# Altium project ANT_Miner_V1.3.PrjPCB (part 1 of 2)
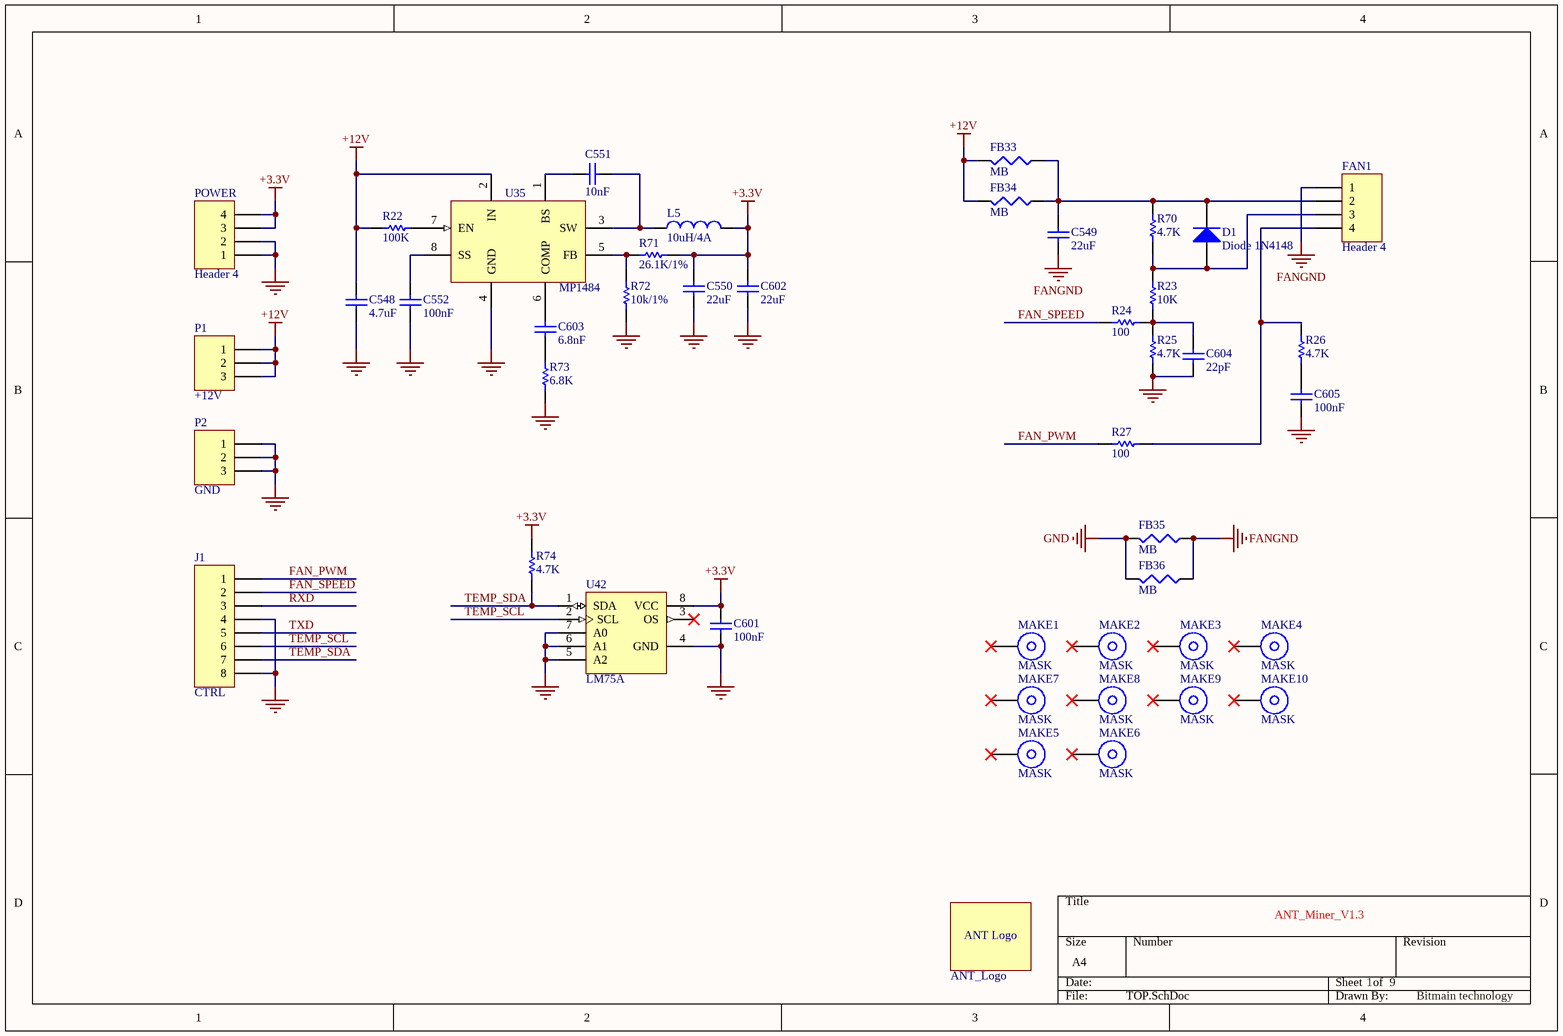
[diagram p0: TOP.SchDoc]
9 sheets, 987 parts. Net scope: global (net labels, ports and power ports of the same name join across sheets).
Board file: BitMainTech_V1.3.PcbDoc
Sheets:
  TOP.SchDoc
  HashPower1.SchDoc
  HashPower2.SchDoc
  HashPower3.SchDoc
  HashPower4.SchDoc
  HashUnit1.SchDoc
  HashUnit2.SchDoc
  HashUnit3.SchDoc
  HashUnit4.SchDoc

## Sheet TOP.SchDoc: ANT_Miner_V1.3
size A4; Date: 2013/11/20; DrawnBy: Bitmain technology; SheetNumber: 1; SheetTotal: 9

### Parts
C548  4.7uF  [CAP1210(3225)_TAN]
C549  22uF  [CAP1210(3225)_TAN]
C550  22uF  [CAP1210(3225)_TAN]
C551  10nF  [CC0603(1608)]
C552  100nF  [CC0603(1608)]
C601  100nF  [CC0603(1608)]
C602  22uF  [CAP1210(3225)_TAN]
C603  6.8nF  [CC0603(1608)]
C604  22pF  [CC0603(1608)]
C605  100nF  [CC0603(1608)]
D1  Diode 1N4148  [CD3216-1206]
FAN1  Header 4  [4PINFAN]
FB33  MB  [INDC3216L]
FB34  MB  [INDC3216L]
FB35  MB  [INDC3216L]
FB36  MB  [INDC3216L]
J1  CTRL  [8Pin_180]
L5  10uH/4A  [SMD_L_7.4x7.4]
MAKE1  MASK  [MASK]
MAKE2  MASK  [MASK]
MAKE3  MASK  [MASK]
MAKE4  MASK  [MASK]
MAKE5  MASK  [MASK]
MAKE6  MASK  [MASK]
MAKE7  MASK  [MASK]
MAKE8  MASK  [MASK]
MAKE9  MASK  [MASK]
MAKE10  MASK  [MASK]
P1  +12V  [TERMINAL_3]
P2  GND  [TERMINAL_3]
POWER  Header 4  [4Pin_180]
R22  100K  [RR0603(1608)]
R23  10K  [RR0603(1608)]
R24  100  [RR0603(1608)]
R25  4.7K  [RR0603(1608)]
R26  4.7K  [RR0603(1608)]
R27  100  [RR0603(1608)]
R70  4.7K  [RR0603(1608)]
R71  26.1K/1%  [RR0603(1608)]
R72  10k/1%  [RR0603(1608)]
R73  6.8K  [RR0603(1608)]
R74  4.7K  [RR0603(1608)]
U35  MP1484  [SOIC8L]
U42  LM75A  [SO8_L]
  ANT_Logo  [ANT_Logo_930x370]

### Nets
+3.3V: C550.2 C601.1 C602.2 L5.2 POWER.3 POWER.4 R71.1 R74.2 U42.8(VCC)
+12V: C548.2 FB33.2 FB34.2 P1.1 P1.2 P1.3 R22.2 U35.2(IN)
FANGND: C549.1 FAN1.1 FB35.1 FB36.1
GND: C548.1 C550.1 C552.2 C601.2 C602.1 C604.2 C605.2 FB35.2 FB36.2 J1.4 J1.8 P2.1 P2.2 P2.3 POWER.1 POWER.2 R25.1 R72.1 R73.1 U35.0 U35.4(GND) U42.4(GND) U42.5(A2) U42.6(A1) U42.7(A0)
FAN_PWM: J1.1 R27.2
FAN_SPEED: J1.2 R24.2
RXD: J1.3
TEMP_SCL: J1.6 U42.2(SCL)
TEMP_SDA: J1.7 R74.1 U42.1(SDA)
TXD: J1.5
NetC549_2: C549.2 D1.2(K) FAN1.2 FB33.1 FB34.1 R70.2
NetC551_1: C551.1 U35.1(BS)
NetC551_2: C551.2 L5.1 U35.3(SW)
NetC552_1: C552.1 U35.8(SS)
NetC603_1: C603.1 U35.6(COMP)
NetC603_2: C603.2 R73.2
NetC604_1: C604.1 R23.2 R24.1 R25.2
NetC605_1: C605.1 R26.1
NetD1_1: D1.1(A) FAN1.3 R23.1 R70.1
NetFAN1_4: FAN1.4 R26.2 R27.1
NetR22_1: R22.1 U35.7(EN)
NetR71_2: R71.2 R72.2 U35.5(FB)

Not connected (* = marked no-connect by the designer): MAKE1 1*; MAKE2 1*; MAKE3 1*; MAKE4 1*; MAKE5 1*; MAKE6 1*; MAKE7 1*; MAKE8 1*; MAKE9 1*; MAKE10 1*; U42 3(OS)*

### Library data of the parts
C548-C552 C601-C605 = Cap Semi: Capacitor (Semiconductor SIM Model)
D1 = Diode 1N4148: High Conductance Fast Diode
FAN1 POWER = Header 4: Header, 4-Pin
FB33-FB36 = Res3: Resistor
J1 = Header 8: Header, 8-Pin
L5 = Inductor: Code_IEC: 1005
P1 P2 = Header 3: Header, 3-Pin
R22-R27 R70-R74 = Res1: Resistor
U42 = LM75A: NXP Digital temperature sensor and thermal watchdog

## Sheet HashPower1.SchDoc: ANT_Miner_V1.3
size A4; Date: 2013/11/20; DrawnBy: Bitmain Technology; SheetNumber: 2; SheetTotal: 9
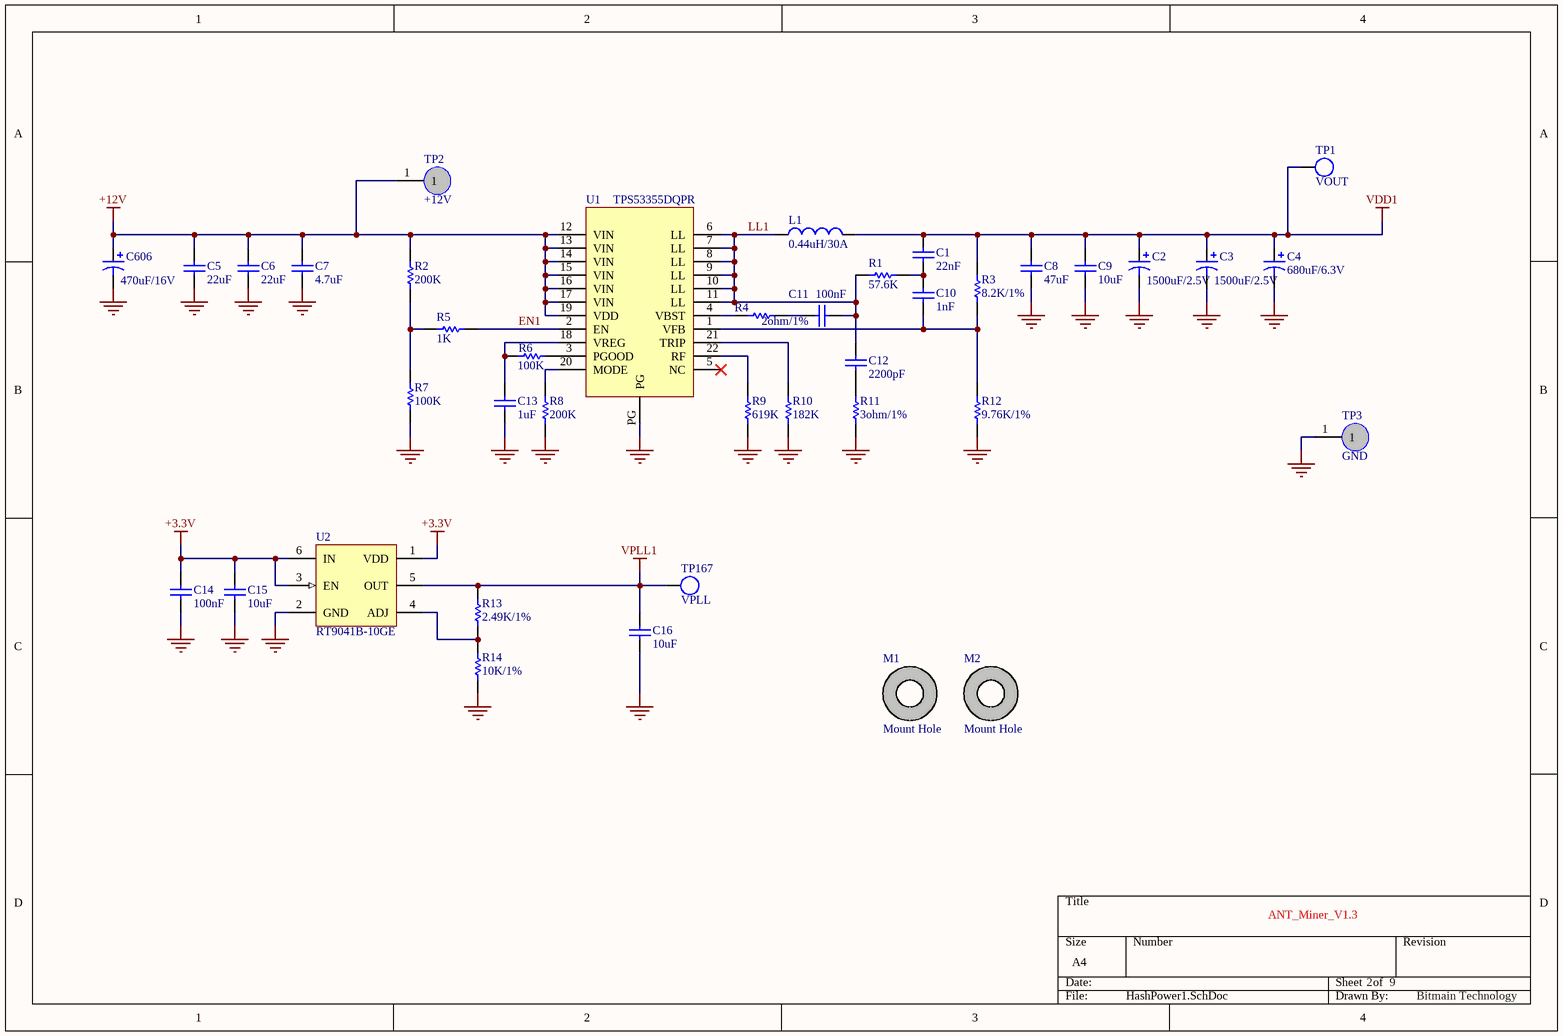
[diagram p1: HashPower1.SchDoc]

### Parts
C1  22nF  [CC0603(1608)]
C2  value 1500uF/2.5V  [F12]  (hidden comment: 1500uF/4V)
C3  value 1500uF/2.5V  [F12]  (hidden comment: 1500uF/4V)
C4  680uF/6.3V  [D]
C5  22uF  [CC1210(3225)]
C6  22uF  [CC1210(3225)]
C7  4.7uF  [CC0805(2012)]
C8  47uF  [CAPC3225L]
C9  10uF  [CAPC2012L]
C10  1nF  [CC0603(1608)]
C11  100nF  [CC0603(1608)]
C12  2200pF  [CC0603(1608)]
C13  1uF  [CC0603(1608)]
C14  100nF  [CC0603(1608)]
C15  10uF  [CC0805(2012)]
C16  10uF  [CC0805(2012)]
C606  470uF/16V  [E12]
L1  0.44uH/30A  [IHLP5050]
M1  Mount Hole  [HOLE_3.2]
M2  Mount Hole  [HOLE_3.2]
R1  57.6K  [RR0603(1608)]
R2  200K  [RR0603(1608)]
R3  8.2K/1%  [RR0603(1608)]
R4  value 2ohm/1%  [RR0603(1608)]  (hidden comment: 2)
R5  1K  [RR0603(1608)]
R6  100K  [RR0603(1608)]
R7  100K  [RR0603(1608)]
R8  200K  [RR0603(1608)]
R9  619K  [RR0603(1608)]
R10  182K  [RR0603(1608)]
R11  value 3ohm/1%  [RR0603(1608)]  (hidden comment: 3)
R12  9.76K/1%  [RR0603(1608)]
R13  2.49K/1%  [RR0603(1608)]
R14  10K/1%  [RR0603(1608)]
TP1  VOUT  [TP_SMD_1.0]
TP2  +12V  [TP]
TP3  GND  [TP]
TP167  VPLL  [TP_SMD_1.0]
U1  TPS53355DQPR  [TPS53355]
U2  RT9041B-10GE  [SOT23-6_L]

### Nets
+3.3V: C14.2 C15.2 U2.1(VDD) U2.3(EN) U2.6(IN)
+12V: C5.1 C6.1 C7.1 C606.1 R2.1 TP2.1 U1.12(VIN) U1.13(VIN) U1.14(VIN) U1.15(VIN) U1.16(VIN) U1.17(VIN) U1.19(VDD)
GND: C2.2 C3.2 C4.2 C5.2 C6.2 C7.2 C8.1 C9.1 C13.2 C14.1 C15.1 C16.1 C606.2 R7.2 R8.2 R9.2 R10.2 R11.2 R12.2 R14.1 TP3.1 U1.PG U2.2(GND)
VDD1: C1.1 C2.1 C3.1 C4.1 C8.2 C9.2 L1.2 R3.1 TP1.1
VPLL1: C16.2 R13.2 TP167.1 U2.5(OUT)
EN1: R5.2 U1.2(EN)
LL1: C11.2 C12.1 L1.1 R1.1 U1.6(LL) U1.7(LL) U1.8(LL) U1.9(LL) U1.10(LL) U1.11(LL)
NetC1_2: C1.2 C10.1 R1.2
NetC10_2: C10.2 R3.2 R12.1 U1.1(VFB)
NetC11_1: C11.1 R4.2
NetC12_2: C12.2 R11.1
NetC13_1: C13.1 R6.1 U1.18(VREG)
NetR2_2: R2.2 R5.1 R7.1
NetR4_1: R4.1 U1.4(VBST)
NetR6_2: R6.2 U1.3(PGOOD)
NetR8_1: R8.1 U1.20(MODE)
NetR9_1: R9.1 U1.22(RF)
NetR10_1: R10.1 U1.21(TRIP)
NetR13_1: R13.1 R14.2 U2.4(ADJ)

Not connected (* = marked no-connect by the designer): M1 0(PIN); M2 0(PIN); U1 5(NC)*

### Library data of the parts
C1 C5-C7 C10-C13 = Cap: Capacitor
C2 C3 C606 = Cap Pol2: Polarized Capacitor (SMD)
C4 = Cap Pol3: Polarized Capacitor (Surface Mount)
C8 C9 C14-C16 = Cap Semi: Capacitor (Semiconductor SIM Model)
L1 = Inductor: Code_IEC: 1005
M1 M2 = M_Hole
R1-R14 = Res1: Resistor
TP1 TP167 = TP: Test Point
TP2 TP3 = TP
U1 = TPS53355: TI DC-DC,Output 30A.

## Sheet HashPower2.SchDoc: ANT_Miner_V1.3
size A4; Date: 2013/11/20; DrawnBy: Bitmain Technology; SheetNumber: 3; SheetTotal: 9
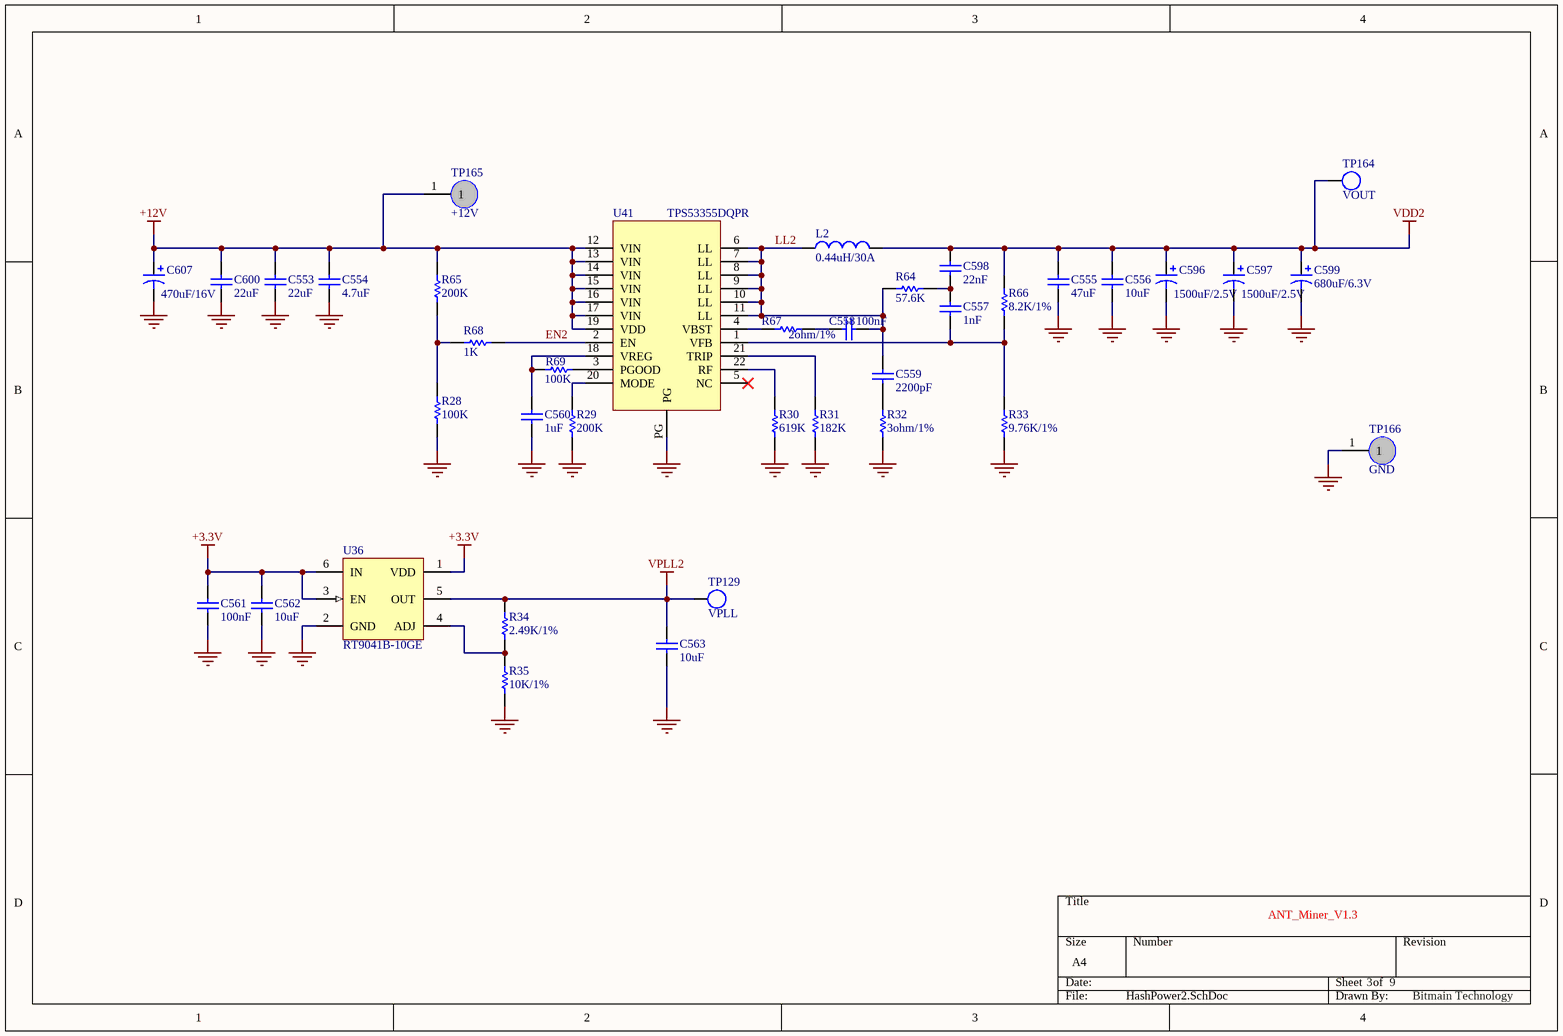
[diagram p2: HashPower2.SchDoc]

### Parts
C553  22uF  [CC1210(3225)]
C554  4.7uF  [CC0805(2012)]
C555  47uF  [CAPC3225L]
C556  10uF  [CAPC2012L]
C557  1nF  [CC0603(1608)]
C558  100nF  [CC0603(1608)]
C559  2200pF  [CC0603(1608)]
C560  1uF  [CC0603(1608)]
C561  100nF  [CC0603(1608)]
C562  10uF  [CC0805(2012)]
C563  10uF  [CC0805(2012)]
C596  value 1500uF/2.5V  [F12]  (hidden comment: 1500uF/4V)
C597  value 1500uF/2.5V  [F12]  (hidden comment: 1500uF/4V)
C598  22nF  [CC0603(1608)]
C599  680uF/6.3V  [D]
C600  22uF  [CC1210(3225)]
C607  470uF/16V  [E12]
L2  0.44uH/30A  [IHLP5050]
R28  100K  [RR0603(1608)]
R29  200K  [RR0603(1608)]
R30  619K  [RR0603(1608)]
R31  182K  [RR0603(1608)]
R32  value 3ohm/1%  [RR0603(1608)]  (hidden comment: 3)
R33  9.76K/1%  [RR0603(1608)]
R34  2.49K/1%  [RR0603(1608)]
R35  10K/1%  [RR0603(1608)]
R64  57.6K  [RR0603(1608)]
R65  200K  [RR0603(1608)]
R66  8.2K/1%  [RR0603(1608)]
R67  value 2ohm/1%  [RR0603(1608)]  (hidden comment: 2)
R68  1K  [RR0603(1608)]
R69  100K  [RR0603(1608)]
TP129  VPLL  [TP_SMD_1.0]
TP164  VOUT  [TP_SMD_1.0]
TP165  +12V  [TP]
TP166  GND  [TP]
U36  RT9041B-10GE  [SOT23-6_L]
U41  TPS53355DQPR  [TPS53355]

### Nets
+3.3V: C561.2 C562.2 U36.1(VDD) U36.3(EN) U36.6(IN)
+12V: C553.1 C554.1 C600.1 C607.1 R65.1 TP165.1 U41.12(VIN) U41.13(VIN) U41.14(VIN) U41.15(VIN) U41.16(VIN) U41.17(VIN) U41.19(VDD)
GND: C553.2 C554.2 C555.1 C556.1 C560.2 C561.1 C562.1 C563.1 C596.2 C597.2 C599.2 C600.2 C607.2 R28.2 R29.2 R30.2 R31.2 R32.2 R33.2 R35.1 TP166.1 U36.2(GND) U41.PG
VDD2: C555.2 C556.2 C596.1 C597.1 C598.1 C599.1 L2.2 R66.1 TP164.1
VPLL2: C563.2 R34.2 TP129.1 U36.5(OUT)
EN2: R68.2 U41.2(EN)
LL2: C558.2 C559.1 L2.1 R64.1 U41.6(LL) U41.7(LL) U41.8(LL) U41.9(LL) U41.10(LL) U41.11(LL)
NetC557_1: C557.1 C598.2 R64.2
NetC557_2: C557.2 R33.1 R66.2 U41.1(VFB)
NetC558_1: C558.1 R67.2
NetC559_2: C559.2 R32.1
NetC560_1: C560.1 R69.1 U41.18(VREG)
NetR28_1: R28.1 R65.2 R68.1
NetR29_1: R29.1 U41.20(MODE)
NetR30_1: R30.1 U41.22(RF)
NetR31_1: R31.1 U41.21(TRIP)
NetR34_1: R34.1 R35.2 U36.4(ADJ)
NetR67_1: R67.1 U41.4(VBST)
NetR69_2: R69.2 U41.3(PGOOD)

Not connected (* = marked no-connect by the designer): U41 5(NC)*

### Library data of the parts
C553 C554 C557-C560 C598 C600 = Cap: Capacitor
C555 C556 C561-C563 = Cap Semi: Capacitor (Semiconductor SIM Model)
C596 C597 C607 = Cap Pol2: Polarized Capacitor (SMD)
C599 = Cap Pol3: Polarized Capacitor (Surface Mount)
L2 = Inductor: Code_IEC: 1005
R28-R35 R64-R69 = Res1: Resistor
TP129 TP164 = TP: Test Point
TP165 TP166 = TP
U41 = TPS53355

## Sheet HashPower3.SchDoc: ANT_Miner_V1.3
size A4; Date: 2013/11/20; DrawnBy: Bitmain Technology; SheetNumber: 4; SheetTotal: 9
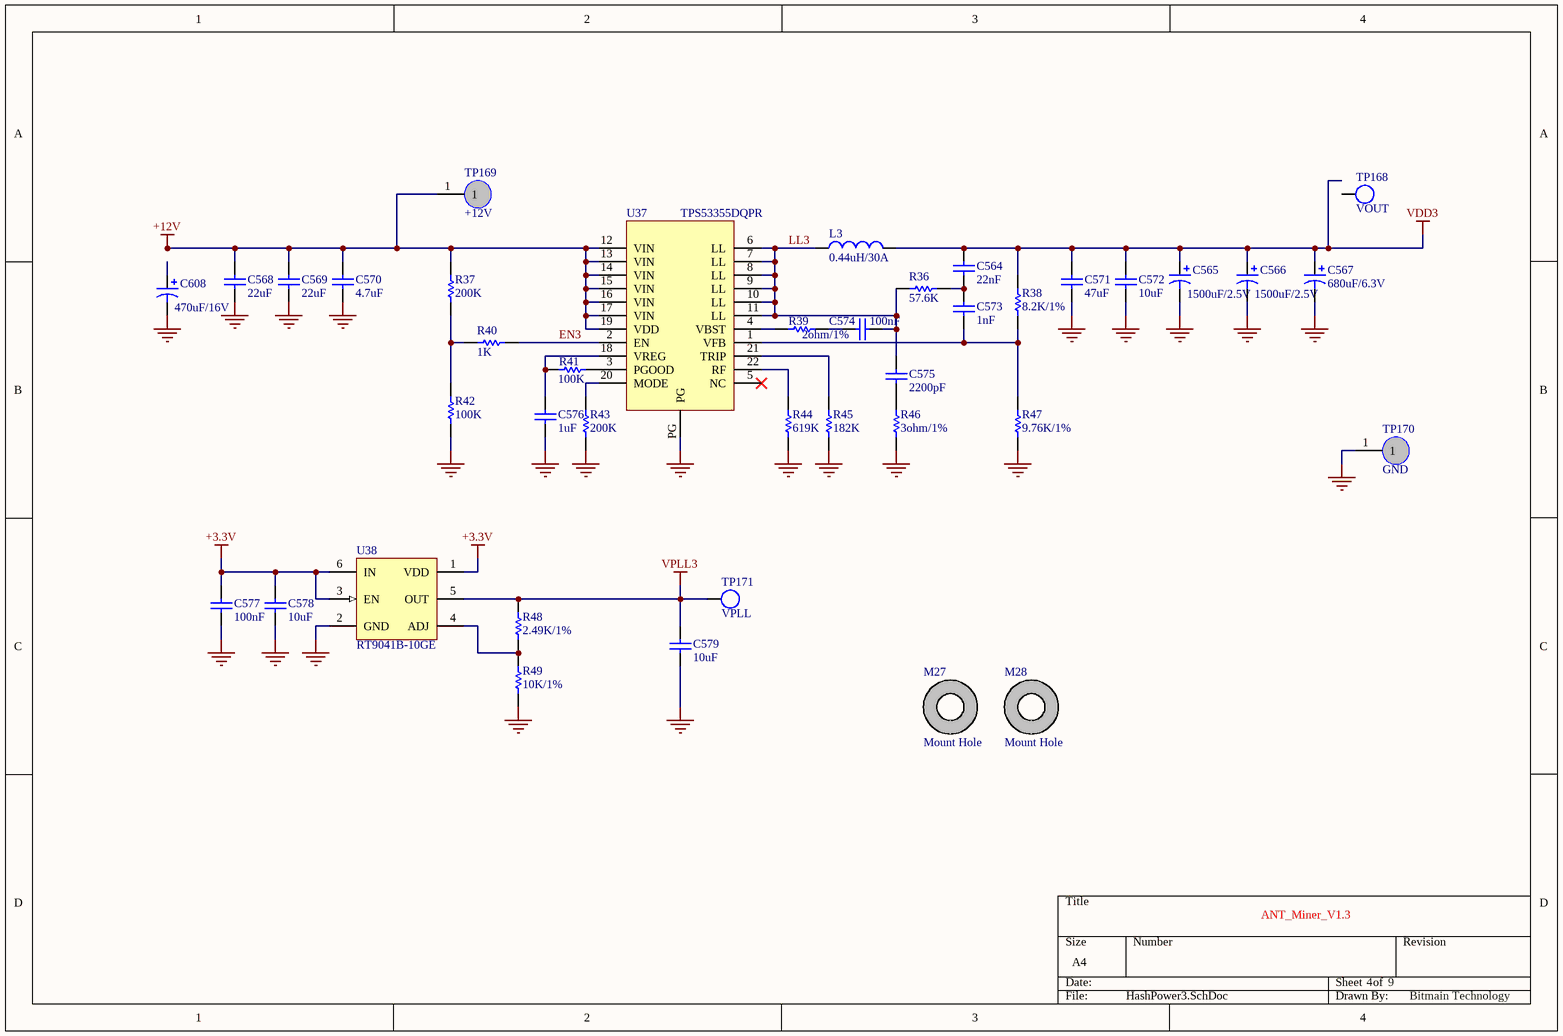
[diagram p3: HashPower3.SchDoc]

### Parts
C564  22nF  [CC0603(1608)]
C565  value 1500uF/2.5V  [F12]  (hidden comment: 1500uF/4V)
C566  value 1500uF/2.5V  [F12]  (hidden comment: 1500uF/4V)
C567  680uF/6.3V  [D]
C568  22uF  [CC1210(3225)]
C569  22uF  [CC1210(3225)]
C570  4.7uF  [CC0805(2012)]
C571  47uF  [CAPC3225L]
C572  10uF  [CAPC2012L]
C573  1nF  [CC0603(1608)]
C574  100nF  [CC0603(1608)]
C575  2200pF  [CC0603(1608)]
C576  1uF  [CC0603(1608)]
C577  100nF  [CC0603(1608)]
C578  10uF  [CC0805(2012)]
C579  10uF  [CC0805(2012)]
C608  470uF/16V  [E12]
L3  0.44uH/30A  [IHLP5050]
M27  Mount Hole  [HOLE_3.2]
M28  Mount Hole  [HOLE_3.2]
R36  57.6K  [RR0603(1608)]
R37  200K  [RR0603(1608)]
R38  8.2K/1%  [RR0603(1608)]
R39  value 2ohm/1%  [RR0603(1608)]  (hidden comment: 2)
R40  1K  [RR0603(1608)]
R41  100K  [RR0603(1608)]
R42  100K  [RR0603(1608)]
R43  200K  [RR0603(1608)]
R44  619K  [RR0603(1608)]
R45  182K  [RR0603(1608)]
R46  value 3ohm/1%  [RR0603(1608)]  (hidden comment: 3)
R47  9.76K/1%  [RR0603(1608)]
R48  2.49K/1%  [RR0603(1608)]
R49  10K/1%  [RR0603(1608)]
TP168  VOUT  [TP_SMD_1.0]
TP169  +12V  [TP]
TP170  GND  [TP]
TP171  VPLL  [TP_SMD_1.0]
U37  TPS53355DQPR  [TPS53355]
U38  RT9041B-10GE  [SOT23-6_L]

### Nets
+3.3V: C577.2 C578.2 U38.1(VDD) U38.3(EN) U38.6(IN)
+12V: C568.1 C569.1 C570.1 R37.1 TP169.1 U37.12(VIN) U37.13(VIN) U37.14(VIN) U37.15(VIN) U37.16(VIN) U37.17(VIN) U37.19(VDD)
GND: C565.2 C566.2 C567.2 C568.2 C569.2 C570.2 C571.1 C572.1 C576.2 C577.1 C578.1 C579.1 C608.2 R42.2 R43.2 R44.2 R45.2 R46.2 R47.2 R49.1 TP170.1 U37.PG U38.2(GND)
VDD3: C564.1 C565.1 C566.1 C567.1 C571.2 C572.2 L3.2 R38.1
VPLL3: C579.2 R48.2 TP171.1 U38.5(OUT)
EN3: R40.2 U37.2(EN)
LL3: C574.2 C575.1 L3.1 R36.1 U37.6(LL) U37.7(LL) U37.8(LL) U37.9(LL) U37.10(LL) U37.11(LL)
NetC564_2: C564.2 C573.1 R36.2
NetC573_2: C573.2 R38.2 R47.1 U37.1(VFB)
NetC574_1: C574.1 R39.2
NetC575_2: C575.2 R46.1
NetC576_1: C576.1 R41.1 U37.18(VREG)
NetR37_2: R37.2 R40.1 R42.1
NetR39_1: R39.1 U37.4(VBST)
NetR41_2: R41.2 U37.3(PGOOD)
NetR43_1: R43.1 U37.20(MODE)
NetR44_1: R44.1 U37.22(RF)
NetR45_1: R45.1 U37.21(TRIP)
NetR48_1: R48.1 R49.2 U38.4(ADJ)

Not connected (* = marked no-connect by the designer): C608 1; M27 0(PIN); M28 0(PIN); TP168 1; U37 5(NC)*

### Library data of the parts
C564 C568-C570 C573-C576 = Cap: Capacitor
C565 C566 C608 = Cap Pol2: Polarized Capacitor (SMD)
C567 = Cap Pol3: Polarized Capacitor (Surface Mount)
C571 C572 C577-C579 = Cap Semi: Capacitor (Semiconductor SIM Model)
L3 = Inductor: Code_IEC: 1005
M27 M28 = M_Hole
R36-R49 = Res1: Resistor
TP168 TP171 = TP: Test Point
TP169 TP170 = TP
U37 = TPS53355

## Sheet HashPower4.SchDoc: ANT_Miner_V1.3
size A4; Date: 2013/11/20; DrawnBy: Bitmain Technology; SheetNumber: 5; SheetTotal: 9
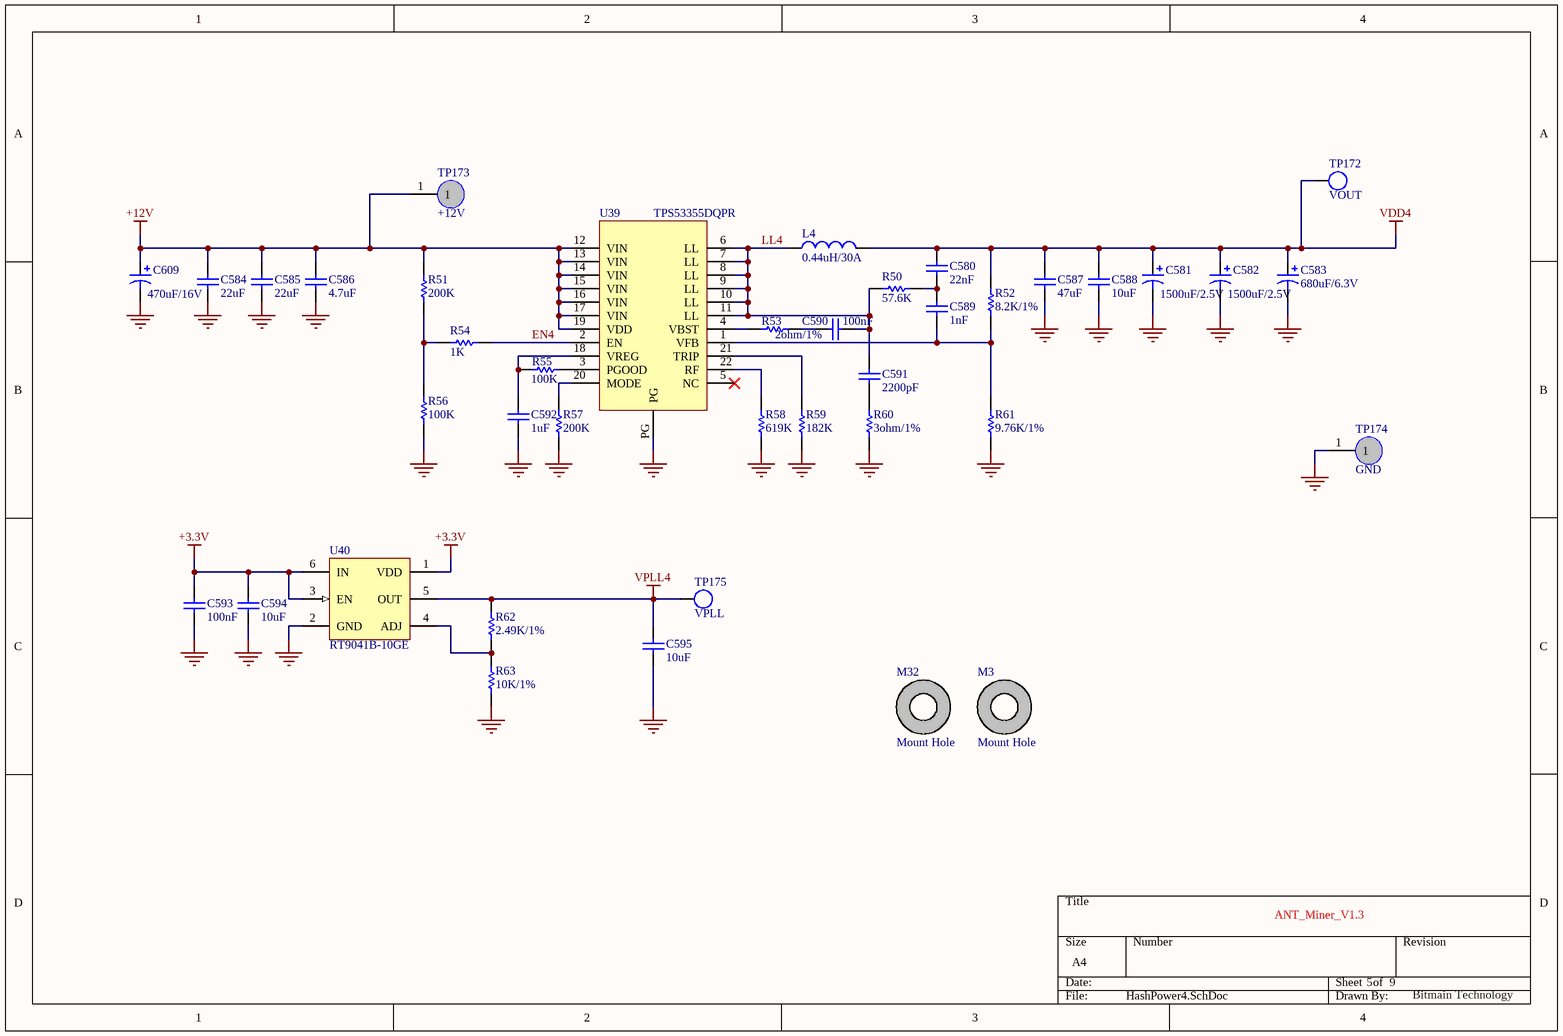
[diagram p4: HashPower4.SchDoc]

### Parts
C580  22nF  [CC0603(1608)]
C581  value 1500uF/2.5V  [F12]  (hidden comment: 1500uF/4V)
C582  value 1500uF/2.5V  [F12]  (hidden comment: 1500uF/4V)
C583  680uF/6.3V  [D]
C584  22uF  [CC1210(3225)]
C585  22uF  [CC1210(3225)]
C586  4.7uF  [CC0805(2012)]
C587  47uF  [CAPC3225L]
C588  10uF  [CAPC2012L]
C589  1nF  [CC0603(1608)]
C590  100nF  [CC0603(1608)]
C591  2200pF  [CC0603(1608)]
C592  1uF  [CC0603(1608)]
C593  100nF  [CC0603(1608)]
C594  10uF  [CC0805(2012)]
C595  10uF  [CC0805(2012)]
C609  470uF/16V  [E12]
L4  0.44uH/30A  [IHLP5050]
M3  Mount Hole  [HOLE_3.2]
M32  Mount Hole  [HOLE_3.2]
R50  57.6K  [RR0603(1608)]
R51  200K  [RR0603(1608)]
R52  8.2K/1%  [RR0603(1608)]
R53  value 2ohm/1%  [RR0603(1608)]  (hidden comment: 2)
R54  1K  [RR0603(1608)]
R55  100K  [RR0603(1608)]
R56  100K  [RR0603(1608)]
R57  200K  [RR0603(1608)]
R58  619K  [RR0603(1608)]
R59  182K  [RR0603(1608)]
R60  value 3ohm/1%  [RR0603(1608)]  (hidden comment: 3)
R61  9.76K/1%  [RR0603(1608)]
R62  2.49K/1%  [RR0603(1608)]
R63  10K/1%  [RR0603(1608)]
TP172  VOUT  [TP_SMD_1.0]
TP173  +12V  [TP]
TP174  GND  [TP]
TP175  VPLL  [TP_SMD_1.0]
U39  TPS53355DQPR  [TPS53355]
U40  RT9041B-10GE  [SOT23-6_L]

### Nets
+3.3V: C593.2 C594.2 U40.1(VDD) U40.3(EN) U40.6(IN)
+12V: C584.1 C585.1 C586.1 C609.1 R51.1 TP173.1 U39.12(VIN) U39.13(VIN) U39.14(VIN) U39.15(VIN) U39.16(VIN) U39.17(VIN) U39.19(VDD)
GND: C581.2 C582.2 C583.2 C584.2 C585.2 C586.2 C587.1 C588.1 C592.2 C593.1 C594.1 C595.1 C609.2 R56.2 R57.2 R58.2 R59.2 R60.2 R61.2 R63.1 TP174.1 U39.PG U40.2(GND)
VDD4: C580.1 C581.1 C582.1 C583.1 C587.2 C588.2 L4.2 R52.1 TP172.1
VPLL4: C595.2 R62.2 TP175.1 U40.5(OUT)
EN4: R54.2 U39.2(EN)
LL4: C590.2 C591.1 L4.1 R50.1 U39.6(LL) U39.7(LL) U39.8(LL) U39.9(LL) U39.10(LL) U39.11(LL)
NetC580_2: C580.2 C589.1 R50.2
NetC589_2: C589.2 R52.2 R61.1 U39.1(VFB)
NetC590_1: C590.1 R53.2
NetC591_2: C591.2 R60.1
NetC592_1: C592.1 R55.1 U39.18(VREG)
NetR51_2: R51.2 R54.1 R56.1
NetR53_1: R53.1 U39.4(VBST)
NetR55_2: R55.2 U39.3(PGOOD)
NetR57_1: R57.1 U39.20(MODE)
NetR58_1: R58.1 U39.22(RF)
NetR59_1: R59.1 U39.21(TRIP)
NetR62_1: R62.1 R63.2 U40.4(ADJ)

Not connected (* = marked no-connect by the designer): M3 0(PIN); M32 0(PIN); U39 5(NC)*

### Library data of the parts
C580 C584-C586 C589-C592 = Cap: Capacitor
C581 C582 C609 = Cap Pol2: Polarized Capacitor (SMD)
C583 = Cap Pol3: Polarized Capacitor (Surface Mount)
C587 C588 C593-C595 = Cap Semi: Capacitor (Semiconductor SIM Model)
L4 = Inductor: Code_IEC: 1005
M3 M32 = M_Hole
R50-R63 = Res1: Resistor
TP172 TP175 = TP: Test Point
TP173 TP174 = TP
U39 = TPS53355

## Sheet HashUnit1.SchDoc: ANT_Miner_V1.3
size A2; Date: 2013/11/20; DrawnBy: Bitmain Technology; SheetNumber: 6; SheetTotal: 9
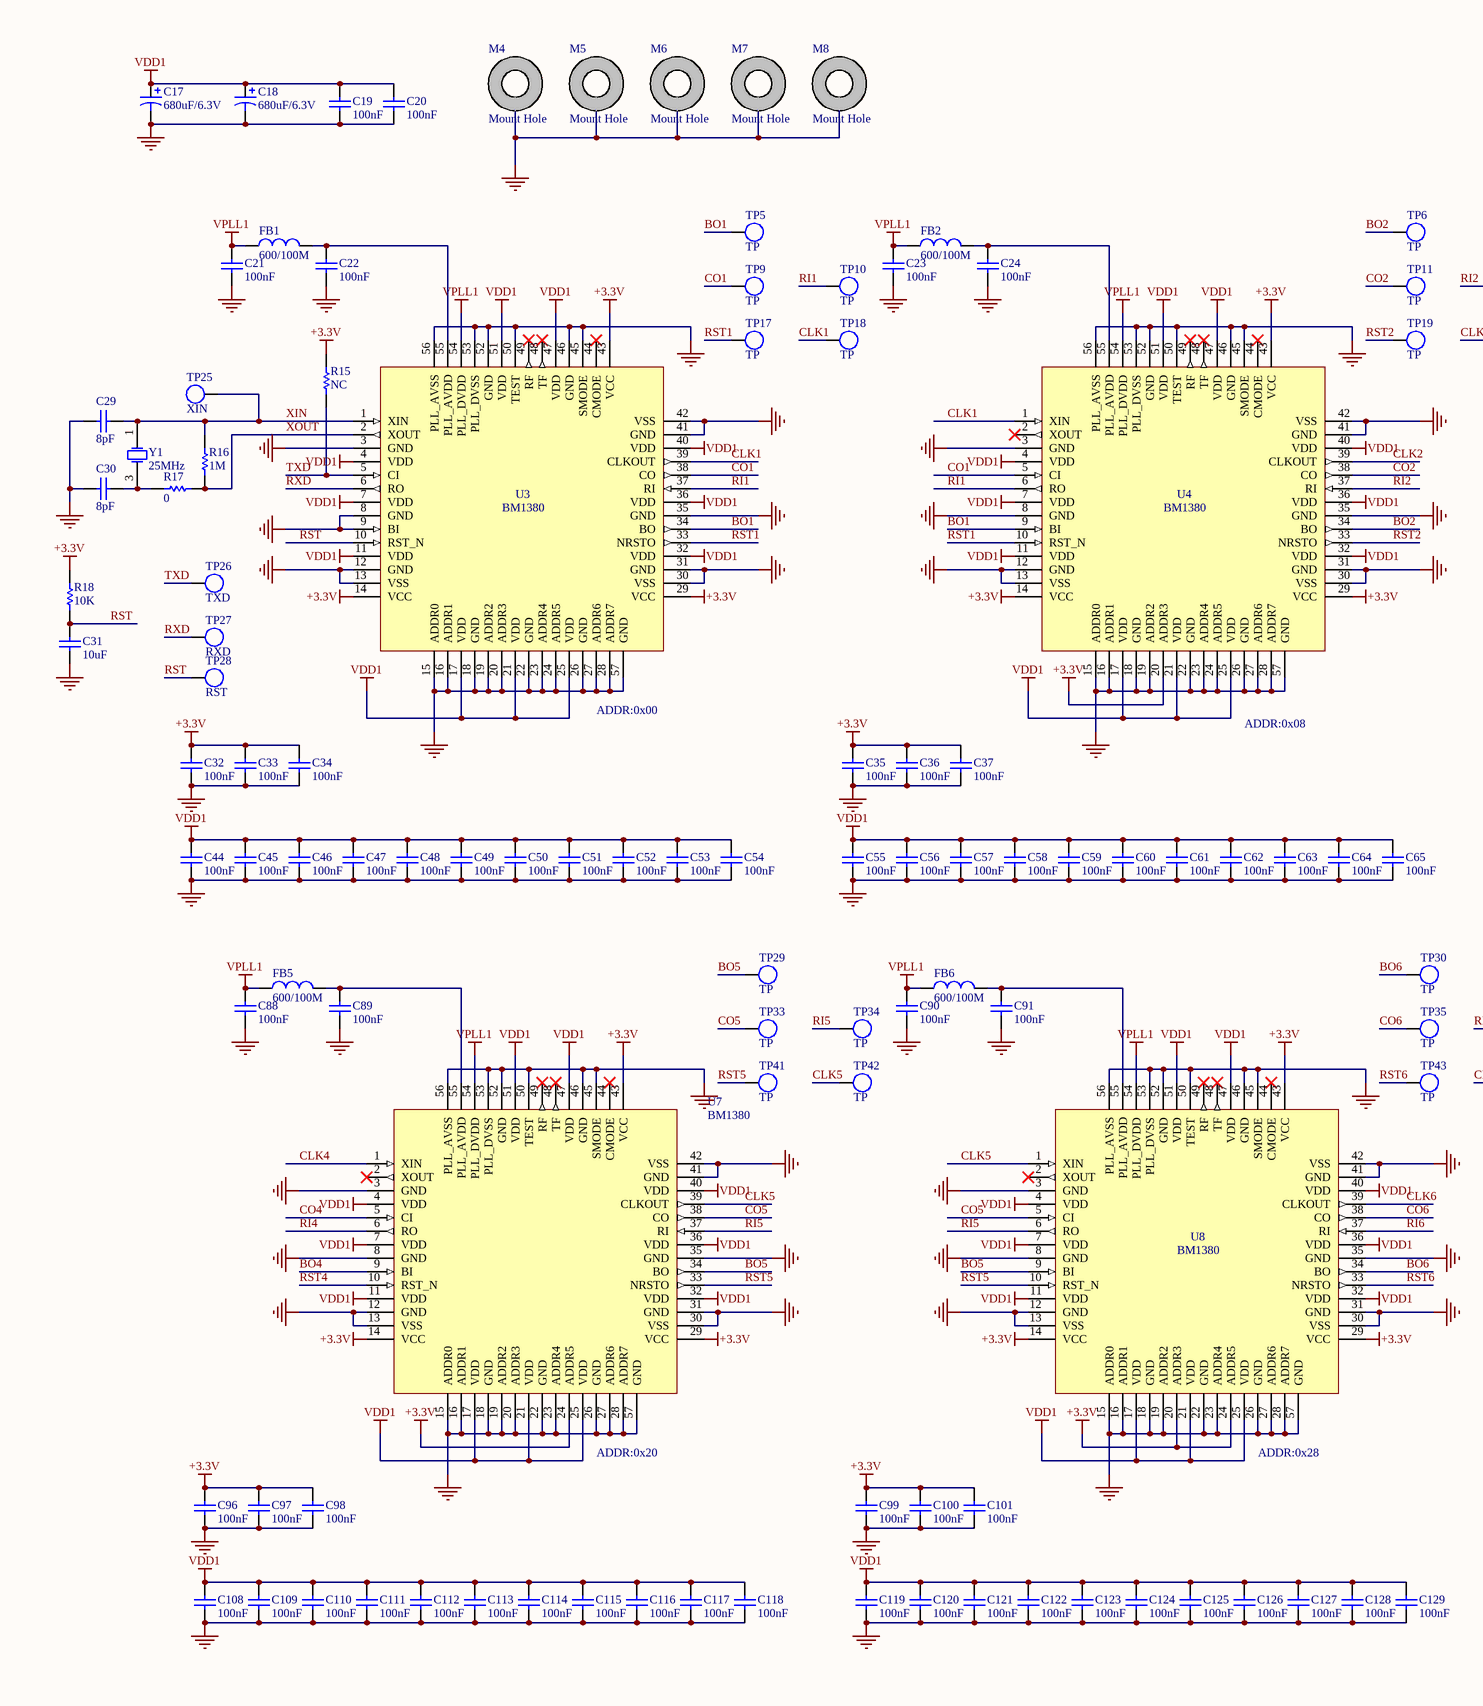
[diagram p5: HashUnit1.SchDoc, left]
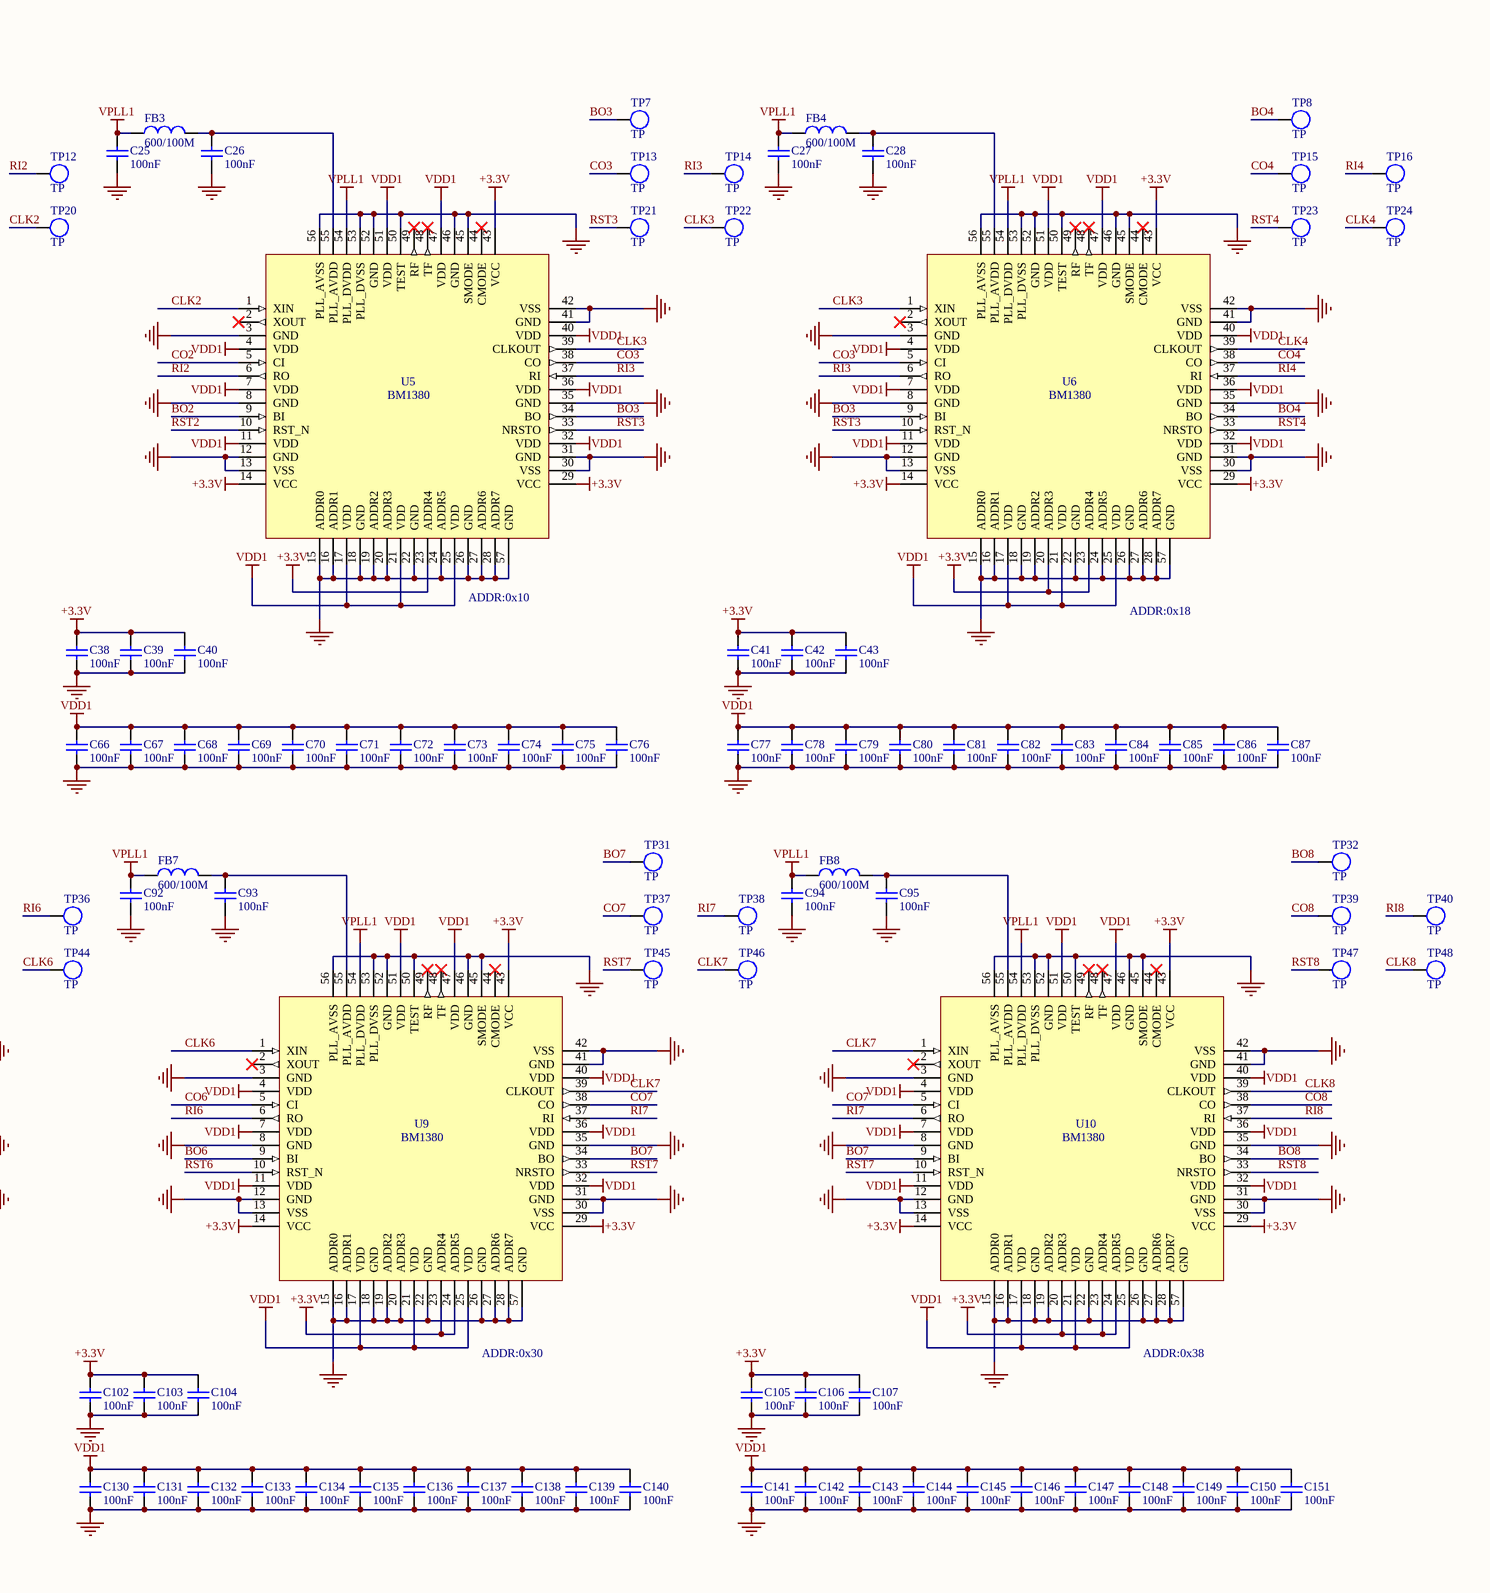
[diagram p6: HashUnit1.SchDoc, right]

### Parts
C17  680uF/6.3V  [D]
C18  680uF/6.3V  [D]
C19  100nF  [CC0603(1608)]
C20  100nF  [CC0603(1608)]
C21  100nF  [CC0603(1608)]
C22  100nF  [CC0603(1608)]
C23  100nF  [CC0603(1608)]
C24  100nF  [CC0603(1608)]
C25  100nF  [CC0603(1608)]
C26  100nF  [CC0603(1608)]
C27  100nF  [CC0603(1608)]
C28  100nF  [CC0603(1608)]
C29  8pF  [CC0603(1608)]
C30  8pF  [CC0603(1608)]
C31  10uF  [CC0603(1608)]
C32  100nF  [CC0603(1608)]
C33  100nF  [CC0603(1608)]
C34  100nF  [CC0603(1608)]
C35  100nF  [CC0603(1608)]
C36  100nF  [CC0603(1608)]
C37  100nF  [CC0603(1608)]
C38  100nF  [CC0603(1608)]
C39  100nF  [CC0603(1608)]
C40  100nF  [CC0603(1608)]
C41  100nF  [CC0603(1608)]
C42  100nF  [CC0603(1608)]
C43  100nF  [CC0603(1608)]
C44  100nF  [CC0603(1608)]
C45  100nF  [CC0603(1608)]
C46  100nF  [CC0603(1608)]
C47  100nF  [CC0603(1608)]
C48  100nF  [CC0603(1608)]
C49  100nF  [CC0603(1608)]
C50  100nF  [CC0603(1608)]
C51  100nF  [CC0603(1608)]
C52  100nF  [CC0603(1608)]
C53  100nF  [CC0603(1608)]
C54  100nF  [CC0603(1608)]
C55  100nF  [CC0603(1608)]
C56  100nF  [CC0603(1608)]
C57  100nF  [CC0603(1608)]
C58  100nF  [CC0603(1608)]
C59  100nF  [CC0603(1608)]
C60  100nF  [CC0603(1608)]
C61  100nF  [CC0603(1608)]
C62  100nF  [CC0603(1608)]
C63  100nF  [CC0603(1608)]
C64  100nF  [CC0603(1608)]
C65  100nF  [CC0603(1608)]
C66  100nF  [CC0603(1608)]
C67  100nF  [CC0603(1608)]
C68  100nF  [CC0603(1608)]
C69  100nF  [CC0603(1608)]
C70  100nF  [CC0603(1608)]
C71  100nF  [CC0603(1608)]
C72  100nF  [CC0603(1608)]
C73  100nF  [CC0603(1608)]
C74  100nF  [CC0603(1608)]
C75  100nF  [CC0603(1608)]
C76  100nF  [CC0603(1608)]
C77  100nF  [CC0603(1608)]
C78  100nF  [CC0603(1608)]
C79  100nF  [CC0603(1608)]
C80  100nF  [CC0603(1608)]
C81  100nF  [CC0603(1608)]
C82  100nF  [CC0603(1608)]
C83  100nF  [CC0603(1608)]
C84  100nF  [CC0603(1608)]
C85  100nF  [CC0603(1608)]
C86  100nF  [CC0603(1608)]
C87  100nF  [CC0603(1608)]
C88  100nF  [CC0603(1608)]
C89  100nF  [CC0603(1608)]
C90  100nF  [CC0603(1608)]
C91  100nF  [CC0603(1608)]
C92  100nF  [CC0603(1608)]
C93  100nF  [CC0603(1608)]
C94  100nF  [CC0603(1608)]
C95  100nF  [CC0603(1608)]
C96  100nF  [CC0603(1608)]
C97  100nF  [CC0603(1608)]
C98  100nF  [CC0603(1608)]
C99  100nF  [CC0603(1608)]
C100  100nF  [CC0603(1608)]
C101  100nF  [CC0603(1608)]
C102  100nF  [CC0603(1608)]
C103  100nF  [CC0603(1608)]
C104  100nF  [CC0603(1608)]
C105  100nF  [CC0603(1608)]
C106  100nF  [CC0603(1608)]
C107  100nF  [CC0603(1608)]
C108  100nF  [CC0603(1608)]
C109  100nF  [CC0603(1608)]
C110  100nF  [CC0603(1608)]
C111  100nF  [CC0603(1608)]
C112  100nF  [CC0603(1608)]
C113  100nF  [CC0603(1608)]
C114  100nF  [CC0603(1608)]
C115  100nF  [CC0603(1608)]
C116  100nF  [CC0603(1608)]
C117  100nF  [CC0603(1608)]
C118  100nF  [CC0603(1608)]
C119  100nF  [CC0603(1608)]
C120  100nF  [CC0603(1608)]
C121  100nF  [CC0603(1608)]
C122  100nF  [CC0603(1608)]
C123  100nF  [CC0603(1608)]
C124  100nF  [CC0603(1608)]
C125  100nF  [CC0603(1608)]
C126  100nF  [CC0603(1608)]
C127  100nF  [CC0603(1608)]
C128  100nF  [CC0603(1608)]
C129  100nF  [CC0603(1608)]
C130  100nF  [CC0603(1608)]
C131  100nF  [CC0603(1608)]
C132  100nF  [CC0603(1608)]
C133  100nF  [CC0603(1608)]
C134  100nF  [CC0603(1608)]
C135  100nF  [CC0603(1608)]
C136  100nF  [CC0603(1608)]
C137  100nF  [CC0603(1608)]
C138  100nF  [CC0603(1608)]
C139  100nF  [CC0603(1608)]
C140  100nF  [CC0603(1608)]
C141  100nF  [CC0603(1608)]
C142  100nF  [CC0603(1608)]
C143  100nF  [CC0603(1608)]
C144  100nF  [CC0603(1608)]
C145  100nF  [CC0603(1608)]
C146  100nF  [CC0603(1608)]
C147  100nF  [CC0603(1608)]
C148  100nF  [CC0603(1608)]
C149  100nF  [CC0603(1608)]
C150  100nF  [CC0603(1608)]
C151  100nF  [CC0603(1608)]
FB1  600/100M  [FB0603(1608)]
FB2  600/100M  [FB0603(1608)]
FB3  600/100M  [FB0603(1608)]
FB4  600/100M  [FB0603(1608)]
FB5  600/100M  [FB0603(1608)]
FB6  600/100M  [FB0603(1608)]
FB7  600/100M  [FB0603(1608)]
FB8  600/100M  [FB0603(1608)]
M4  Mount Hole  [MHOLE2]
M5  Mount Hole  [MHOLE2]
M6  Mount Hole  [MHOLE2]
M7  Mount Hole  [MHOLE2]
M8  Mount Hole  [MHOLE2]
R15  NC  [RR0603(1608)]
R16  1M  [RR0603(1608)]
R17  0  [RR0603(1608)]
R18  10K  [RR0603(1608)]
TP5  TP  [TP_SMD]
TP6  TP  [TP_SMD]
TP7  TP  [TP_SMD]
TP8  TP  [TP_SMD]
TP9  TP  [TP_SMD]
TP10  TP  [TP_SMD]
TP11  TP  [TP_SMD]
TP12  TP  [TP_SMD]
TP13  TP  [TP_SMD]
TP14  TP  [TP_SMD]
TP15  TP  [TP_SMD]
TP16  TP  [TP_SMD]
TP17  TP  [TP_SMD]
TP18  TP  [TP_SMD]
TP19  TP  [TP_SMD]
TP20  TP  [TP_SMD]
TP21  TP  [TP_SMD]
TP22  TP  [TP_SMD]
TP23  TP  [TP_SMD]
TP24  TP  [TP_SMD]
TP25  value XIN  [TP_SMD]  (hidden comment: TP)
TP26  value TXD  [TP_SMD]  (hidden comment: TP)
TP27  value RXD  [TP_SMD]  (hidden comment: TP)
TP28  value RST  [TP_SMD]  (hidden comment: TP)
TP29  TP  [TP_SMD]
TP30  TP  [TP_SMD]
TP31  TP  [TP_SMD]
TP32  TP  [TP_SMD]
TP33  TP  [TP_SMD]
TP34  TP  [TP_SMD]
TP35  TP  [TP_SMD]
TP36  TP  [TP_SMD]
TP37  TP  [TP_SMD]
TP38  TP  [TP_SMD]
TP39  TP  [TP_SMD]
TP40  TP  [TP_SMD]
TP41  TP  [TP_SMD]
TP42  TP  [TP_SMD]
TP43  TP  [TP_SMD]
TP44  TP  [TP_SMD]
TP45  TP  [TP_SMD]
TP46  TP  [TP_SMD]
TP47  TP  [TP_SMD]
TP48  TP  [TP_SMD]
U3  BM1380  [QFN56]
U4  BM1380  [QFN56]
U5  BM1380  [QFN56]
U6  BM1380  [QFN56]
U7  BM1380  [QFN56]
U8  BM1380  [QFN56]
U9  BM1380  [QFN56]
U10  BM1380  [QFN56]
Y1  25MHz  [SMX2]

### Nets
+3.3V: C32.2 C33.2 C34.2 C35.2 C36.2 C37.2 C38.2 C39.2 C40.2 C41.2 C42.2 C43.2 C96.2 C97.2 C98.2 C99.2 C100.2 C101.2 C102.2 C103.2 C104.2 C105.2 C106.2 C107.2 R15.1 R18.2 U3.14(VCC) U3.29(VCC) U3.43(VCC) U4.14(VCC) U4.20(ADDR3) U4.29(VCC) U4.43(VCC) U5.14(VCC) U5.23(ADDR4) U5.29(VCC) U5.43(VCC) U6.14(VCC) U6.20(ADDR3) U6.23(ADDR4) U6.29(VCC) U6.43(VCC) U7.14(VCC) U7.24(ADDR5) U7.29(VCC) U7.43(VCC) U8.14(VCC) U8.20(ADDR3) U8.24(ADDR5) U8.29(VCC) U8.43(VCC) U9.14(VCC) U9.23(ADDR4) U9.24(ADDR5) U9.29(VCC) U9.43(VCC) U10.14(VCC) U10.20(ADDR3) U10.23(ADDR4) U10.24(ADDR5) U10.29(VCC) U10.43(VCC)
GND: C17.2 C18.2 C19.1 C20.1 C21.2 C22.1 C23.2 C24.1 C25.2 C26.1 C27.2 C28.1 C29.2 C30.2 C31.2 C32.1 C33.1 C34.1 C35.1 C36.1 C37.1 C38.1 C39.1 C40.1 C41.1 C42.1 C43.1 C44.1 C45.1 C46.1 C47.1 C48.1 C49.1 C50.1 C51.1 C52.1 C53.1 C54.1 C55.1 C56.1 C57.1 C58.1 C59.1 C60.1 C61.1 C62.1 C63.1 C64.1 C65.1 C66.1 C67.1 C68.1 C69.1 C70.1 C71.1 C72.1 C73.1 C74.1 C75.1 C76.1 C77.1 C78.1 C79.1 C80.1 C81.1 C82.1 C83.1 C84.1 C85.1 C86.1 C87.1 C88.2 C89.1 C90.2 C91.1 C92.2 C93.1 C94.2 C95.1 C96.1 C97.1 C98.1 C99.1 C100.1 C101.1 C102.1 C103.1 C104.1 C105.1 C106.1 C107.1 C108.1 C109.1 C110.1 C111.1 C112.1 C113.1 C114.1 C115.1 C116.1 C117.1 C118.1 C119.1 C120.1 C121.1 C122.1 C123.1 C124.1 C125.1 C126.1 C127.1 C128.1 C129.1 C130.1 C131.1 C132.1 C133.1 C134.1 C135.1 C136.1 C137.1 C138.1 C139.1 C140.1 C141.1 C142.1 C143.1 C144.1 C145.1 C146.1 C147.1 C148.1 C149.1 C150.1 C151.1 M4.0(PIN) M5.0(PIN) M6.0(PIN) M7.0(PIN) M8.0(PIN) U3.3(GND) U3.8(GND) U3.9(BI) U3.12(GND) U3.13(VSS) U3.15(ADDR0) U3.16(ADDR1) U3.18(GND) U3.19(ADDR2) U3.20(ADDR3) U3.22(GND) U3.23(ADDR4) U3.24(ADDR5) U3.26(GND) U3.27(ADDR6) U3.28(ADDR7) U3.30(VSS) U3.31(GND) U3.35(GND) U3.41(GND) U3.42(VSS) U3.45(SMODE) U3.46(GND) U3.50(TEST) U3.52(GND) U3.53(PLL_DVSS) U3.56(PLL_AVSS) U3.57(GND) U4.3(GND) U4.8(GND) U4.12(GND) U4.13(VSS) U4.15(ADDR0) U4.16(ADDR1) U4.18(GND) U4.19(ADDR2) U4.22(GND) U4.23(ADDR4) U4.24(ADDR5) U4.26(GND) U4.27(ADDR6) U4.28(ADDR7) U4.30(VSS) U4.31(GND) U4.35(GND) U4.41(GND) U4.42(VSS) U4.45(SMODE) U4.46(GND) U4.50(TEST) U4.52(GND) U4.53(PLL_DVSS) U4.56(PLL_AVSS) U4.57(GND) U5.3(GND) U5.8(GND) U5.12(GND) U5.13(VSS) U5.15(ADDR0) U5.16(ADDR1) U5.18(GND) U5.19(ADDR2) U5.20(ADDR3) U5.22(GND) U5.24(ADDR5) U5.26(GND) U5.27(ADDR6) U5.28(ADDR7) U5.30(VSS) U5.31(GND) U5.35(GND) U5.41(GND) U5.42(VSS) U5.45(SMODE) U5.46(GND) U5.50(TEST) U5.52(GND) U5.53(PLL_DVSS) U5.56(PLL_AVSS) U5.57(GND) U6.3(GND) U6.8(GND) U6.12(GND) U6.13(VSS) U6.15(ADDR0) U6.16(ADDR1) U6.18(GND) U6.19(ADDR2) U6.22(GND) U6.24(ADDR5) U6.26(GND) U6.27(ADDR6) U6.28(ADDR7) U6.30(VSS) U6.31(GND) U6.35(GND) U6.41(GND) U6.42(VSS) U6.45(SMODE) U6.46(GND) U6.50(TEST) U6.52(GND) U6.53(PLL_DVSS) U6.56(PLL_AVSS) U6.57(GND) U7.3(GND) U7.8(GND) U7.12(GND) U7.13(VSS) U7.15(ADDR0) U7.16(ADDR1) U7.18(GND) U7.19(ADDR2) U7.20(ADDR3) U7.22(GND) U7.23(ADDR4) U7.26(GND) U7.27(ADDR6) U7.28(ADDR7) U7.30(VSS) U7.31(GND) U7.35(GND) U7.41(GND) U7.42(VSS) U7.45(SMODE) U7.46(GND) U7.50(TEST) U7.52(GND) U7.53(PLL_DVSS) U7.56(PLL_AVSS) U7.57(GND) U8.3(GND) U8.8(GND) U8.12(GND) U8.13(VSS) U8.15(ADDR0) U8.16(ADDR1) U8.18(GND) U8.19(ADDR2) U8.22(GND) U8.23(ADDR4) U8.26(GND) U8.27(ADDR6) U8.28(ADDR7) U8.30(VSS) U8.31(GND) U8.35(GND) U8.41(GND) U8.42(VSS) U8.45(SMODE) U8.46(GND) U8.50(TEST) U8.52(GND) U8.53(PLL_DVSS) U8.56(PLL_AVSS) U8.57(GND) U9.3(GND) U9.8(GND) U9.12(GND) U9.13(VSS) U9.15(ADDR0) U9.16(ADDR1) U9.18(GND) U9.19(ADDR2) U9.20(ADDR3) U9.22(GND) U9.26(GND) U9.27(ADDR6) U9.28(ADDR7) U9.30(VSS) U9.31(GND) U9.35(GND) U9.41(GND) U9.42(VSS) U9.45(SMODE) U9.46(GND) U9.50(TEST) U9.52(GND) U9.53(PLL_DVSS) U9.56(PLL_AVSS) U9.57(GND) U10.3(GND) U10.8(GND) U10.12(GND) U10.13(VSS) U10.15(ADDR0) U10.16(ADDR1) U10.18(GND) U10.19(ADDR2) U10.22(GND) U10.26(GND) U10.27(ADDR6) U10.28(ADDR7) U10.30(VSS) U10.31(GND) U10.35(GND) U10.41(GND) U10.42(VSS) U10.45(SMODE) U10.46(GND) U10.50(TEST) U10.52(GND) U10.53(PLL_DVSS) U10.56(PLL_AVSS) U10.57(GND)
VDD1: C17.1 C18.1 C19.2 C20.2 C44.2 C45.2 C46.2 C47.2 C48.2 C49.2 C50.2 C51.2 C52.2 C53.2 C54.2 C55.2 C56.2 C57.2 C58.2 C59.2 C60.2 C61.2 C62.2 C63.2 C64.2 C65.2 C66.2 C67.2 C68.2 C69.2 C70.2 C71.2 C72.2 C73.2 C74.2 C75.2 C76.2 C77.2 C78.2 C79.2 C80.2 C81.2 C82.2 C83.2 C84.2 C85.2 C86.2 C87.2 C108.2 C109.2 C110.2 C111.2 C112.2 C113.2 C114.2 C115.2 C116.2 C117.2 C118.2 C119.2 C120.2 C121.2 C122.2 C123.2 C124.2 C125.2 C126.2 C127.2 C128.2 C129.2 C130.2 C131.2 C132.2 C133.2 C134.2 C135.2 C136.2 C137.2 C138.2 C139.2 C140.2 C141.2 C142.2 C143.2 C144.2 C145.2 C146.2 C147.2 C148.2 C149.2 C150.2 C151.2 U3.4(VDD) U3.7(VDD) U3.11(VDD) U3.17(VDD) U3.21(VDD) U3.25(VDD) U3.32(VDD) U3.36(VDD) U3.40(VDD) U3.47(VDD) U3.51(VDD) U4.4(VDD) U4.7(VDD) U4.11(VDD) U4.17(VDD) U4.21(VDD) U4.25(VDD) U4.32(VDD) U4.36(VDD) U4.40(VDD) U4.47(VDD) U4.51(VDD) U5.4(VDD) U5.7(VDD) U5.11(VDD) U5.17(VDD) U5.21(VDD) U5.25(VDD) U5.32(VDD) U5.36(VDD) U5.40(VDD) U5.47(VDD) U5.51(VDD) U6.4(VDD) U6.7(VDD) U6.11(VDD) U6.17(VDD) U6.21(VDD) U6.25(VDD) U6.32(VDD) U6.36(VDD) U6.40(VDD) U6.47(VDD) U6.51(VDD) U7.4(VDD) U7.7(VDD) U7.11(VDD) U7.17(VDD) U7.21(VDD) U7.25(VDD) U7.32(VDD) U7.36(VDD) U7.40(VDD) U7.47(VDD) U7.51(VDD) U8.4(VDD) U8.7(VDD) U8.11(VDD) U8.17(VDD) U8.21(VDD) U8.25(VDD) U8.32(VDD) U8.36(VDD) U8.40(VDD) U8.47(VDD) U8.51(VDD) U9.4(VDD) U9.7(VDD) U9.11(VDD) U9.17(VDD) U9.21(VDD) U9.25(VDD) U9.32(VDD) U9.36(VDD) U9.40(VDD) U9.47(VDD) U9.51(VDD) U10.4(VDD) U10.7(VDD) U10.11(VDD) U10.17(VDD) U10.21(VDD) U10.25(VDD) U10.32(VDD) U10.36(VDD) U10.40(VDD) U10.47(VDD) U10.51(VDD)
VPLL1: C21.1 C23.1 C25.1 C27.1 C88.1 C90.1 C92.1 C94.1 FB1.2 FB2.2 FB3.2 FB4.2 FB5.2 FB6.2 FB7.2 FB8.2 U3.54(PLL_DVDD) U4.54(PLL_DVDD) U5.54(PLL_DVDD) U6.54(PLL_DVDD) U7.54(PLL_DVDD) U8.54(PLL_DVDD) U9.54(PLL_DVDD) U10.54(PLL_DVDD)
BO1: TP5.1 U3.34(BO) U4.9(BI)
BO2: TP6.1 U4.34(BO) U5.9(BI)
BO3: TP7.1 U5.34(BO) U6.9(BI)
BO4: TP8.1 U6.34(BO) U7.9(BI)
BO5: TP29.1 U7.34(BO) U8.9(BI)
BO6: TP30.1 U8.34(BO) U9.9(BI)
BO7: TP31.1 U9.34(BO) U10.9(BI)
BO8: TP32.1 U10.34(BO)
CLK1: TP18.1 U3.39(CLKOUT) U4.1(XIN)
CLK2: TP20.1 U4.39(CLKOUT) U5.1(XIN)
CLK3: TP22.1 U5.39(CLKOUT) U6.1(XIN)
CLK4: TP24.1 U6.39(CLKOUT) U7.1(XIN)
CLK5: TP42.1 U7.39(CLKOUT) U8.1(XIN)
CLK6: TP44.1 U8.39(CLKOUT) U9.1(XIN)
CLK7: TP46.1 U9.39(CLKOUT) U10.1(XIN)
CLK8: TP48.1 U10.39(CLKOUT)
CO1: TP9.1 U3.38(CO) U4.5(CI)
CO2: TP11.1 U4.38(CO) U5.5(CI)
CO3: TP13.1 U5.38(CO) U6.5(CI)
CO4: TP15.1 U6.38(CO) U7.5(CI)
CO5: TP33.1 U7.38(CO) U8.5(CI)
CO6: TP35.1 U8.38(CO) U9.5(CI)
CO7: TP37.1 U9.38(CO) U10.5(CI)
CO8: TP39.1 U10.38(CO)
RI1: TP10.1 U3.37(RI) U4.6(RO)
RI2: TP12.1 U4.37(RI) U5.6(RO)
RI3: TP14.1 U5.37(RI) U6.6(RO)
RI4: TP16.1 U6.37(RI) U7.6(RO)
RI5: TP34.1 U7.37(RI) U8.6(RO)
RI6: TP36.1 U8.37(RI) U9.6(RO)
RI7: TP38.1 U9.37(RI) U10.6(RO)
RI8: TP40.1 U10.37(RI)
RST: C31.1 R18.1 TP28.1 U3.10(RST_N)
RST1: TP17.1 U3.33(NRSTO) U4.10(RST_N)
RST2: TP19.1 U4.33(NRSTO) U5.10(RST_N)
RST3: TP21.1 U5.33(NRSTO) U6.10(RST_N)
RST4: TP23.1 U6.33(NRSTO) U7.10(RST_N)
RST5: TP41.1 U7.33(NRSTO) U8.10(RST_N)
RST6: TP43.1 U8.33(NRSTO) U9.10(RST_N)
RST7: TP45.1 U9.33(NRSTO) U10.10(RST_N)
RST8: TP47.1 U10.33(NRSTO)
RXD: TP27.1 U3.6(RO)
TXD: R15.2 TP26.1 U3.5(CI)
XIN: C29.1 R16.2 TP25.1 U3.1(XIN) Y1.1(OSC1)
XOUT: R16.1 R17.1 U3.2(XOUT)
NetC22_2: C22.2 FB1.1 U3.55(PLL_AVDD)
NetC24_2: C24.2 FB2.1 U4.55(PLL_AVDD)
NetC26_2: C26.2 FB3.1 U5.55(PLL_AVDD)
NetC28_2: C28.2 FB4.1 U6.55(PLL_AVDD)
NetC30_1: C30.1 R17.2 Y1.3(OSC2)
NetC89_2: C89.2 FB5.1 U7.55(PLL_AVDD)
NetC91_2: C91.2 FB6.1 U8.55(PLL_AVDD)
NetC93_2: C93.2 FB7.1 U9.55(PLL_AVDD)
NetC95_2: C95.2 FB8.1 U10.55(PLL_AVDD)

Not connected (* = marked no-connect by the designer): U3 44(CMODE)* 48(TF)* 49(RF)*; U4 2(XOUT)* 44(CMODE)* 48(TF)* 49(RF)*; U5 2(XOUT)* 44(CMODE)* 48(TF)* 49(RF)*; U6 2(XOUT)* 44(CMODE)* 48(TF)* 49(RF)*; U7 2(XOUT)* 44(CMODE)* 48(TF)* 49(RF)*; U8 2(XOUT)* 44(CMODE)* 48(TF)* 49(RF)*; U9 2(XOUT)* 44(CMODE)* 48(TF)* 49(RF)*; U10 2(XOUT)* 44(CMODE)* 48(TF)* 49(RF)*

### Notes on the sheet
- ADDR:0x00
- ADDR:0x08
- ADDR:0x10
- ADDR:0x18
- ADDR:0x20
- ADDR:0x28
- ADDR:0x30
- ADDR:0x38

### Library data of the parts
C17 C18 = T492C: Solid Tantalum Chip Capacitor, T492 Series - CWR11 Style Per Mil-PRF-55365/8
C19 C20 = Cap Semi: Capacitor (Semiconductor SIM Model)
C21-C151 = Cap: Capacitor
FB1-FB8 = FB: Inductor; Code_IEC: 1005
M4-M8 = M_Hole
R15-R18 = Res1: Resistor
TP5-TP48 = TP: Test Point
Y1 = XTAL: Crystal Oscillator

## Sheet HashUnit2.SchDoc: ANT_Miner_V1.3
size A2; Date: 2013/11/20; DrawnBy: Bitmain Technology; SheetNumber: 7; SheetTotal: 9
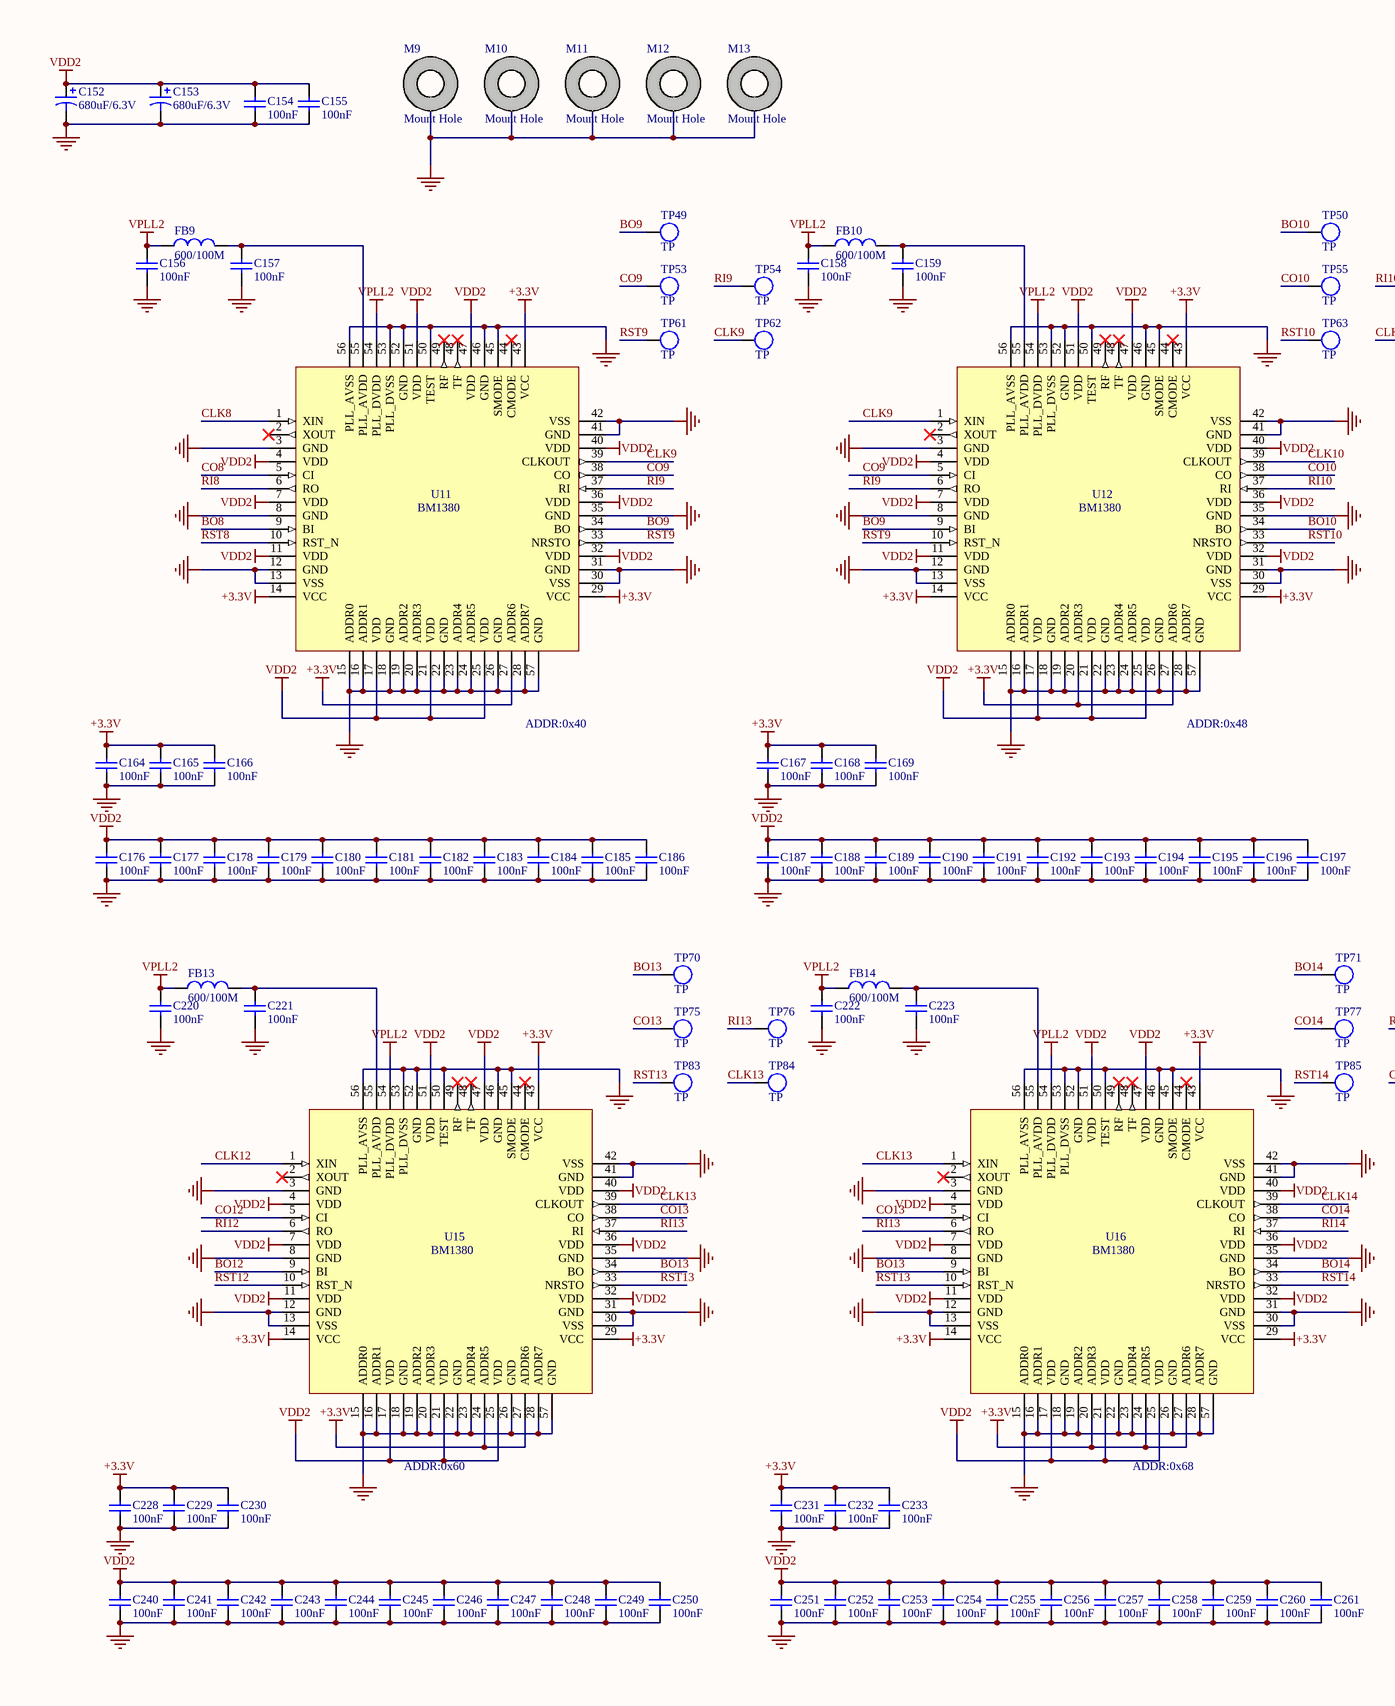
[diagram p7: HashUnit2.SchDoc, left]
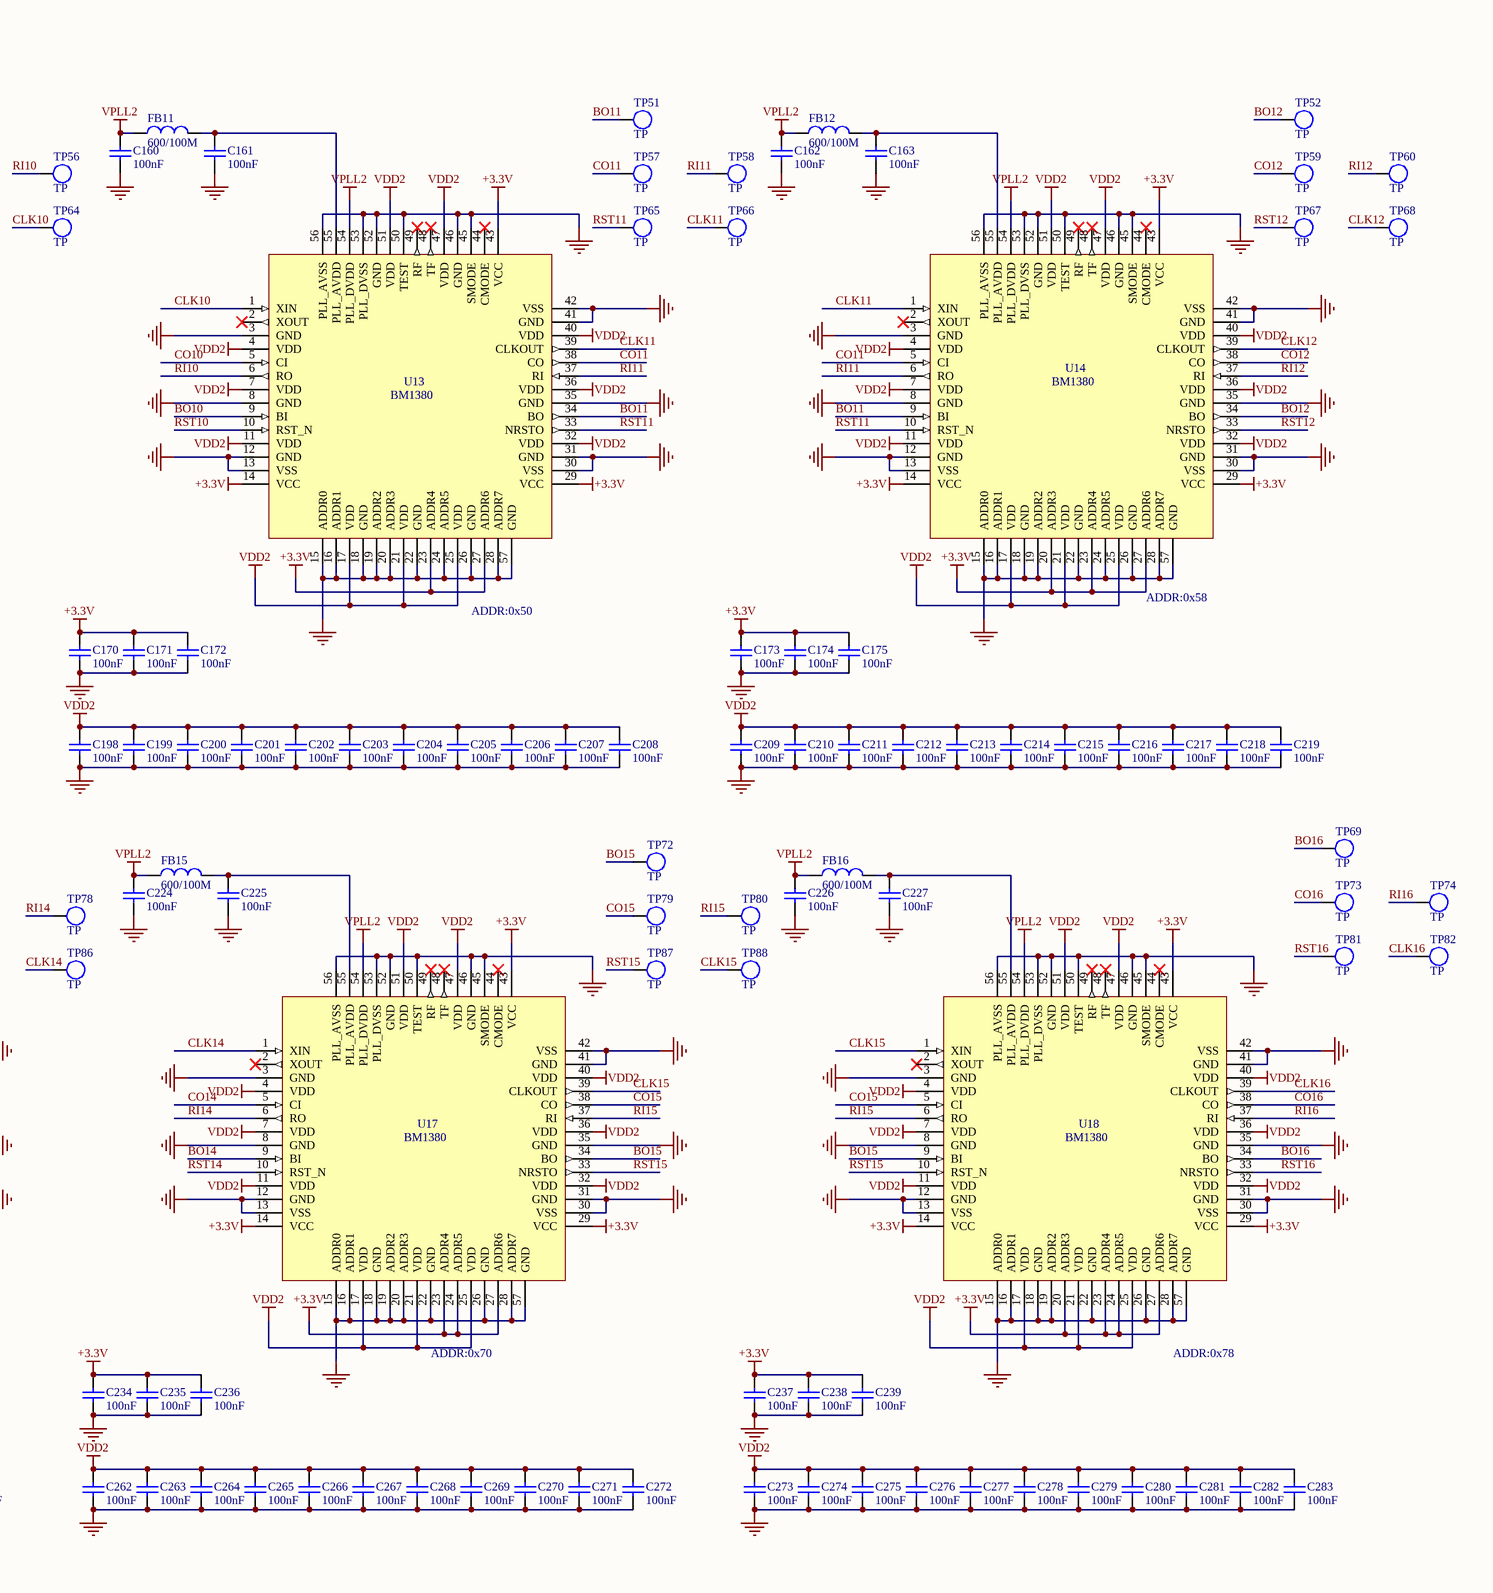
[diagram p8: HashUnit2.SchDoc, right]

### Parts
C152  680uF/6.3V  [D]
C153  680uF/6.3V  [D]
C154  100nF  [CC0603(1608)]
C155  100nF  [CC0603(1608)]
C156  100nF  [CC0603(1608)]
C157  100nF  [CC0603(1608)]
C158  100nF  [CC0603(1608)]
C159  100nF  [CC0603(1608)]
C160  100nF  [CC0603(1608)]
C161  100nF  [CC0603(1608)]
C162  100nF  [CC0603(1608)]
C163  100nF  [CC0603(1608)]
C164  100nF  [CC0603(1608)]
C165  100nF  [CC0603(1608)]
C166  100nF  [CC0603(1608)]
C167  100nF  [CC0603(1608)]
C168  100nF  [CC0603(1608)]
C169  100nF  [CC0603(1608)]
C170  100nF  [CC0603(1608)]
C171  100nF  [CC0603(1608)]
C172  100nF  [CC0603(1608)]
C173  100nF  [CC0603(1608)]
C174  100nF  [CC0603(1608)]
C175  100nF  [CC0603(1608)]
C176  100nF  [CC0603(1608)]
C177  100nF  [CC0603(1608)]
C178  100nF  [CC0603(1608)]
C179  100nF  [CC0603(1608)]
C180  100nF  [CC0603(1608)]
C181  100nF  [CC0603(1608)]
C182  100nF  [CC0603(1608)]
C183  100nF  [CC0603(1608)]
C184  100nF  [CC0603(1608)]
C185  100nF  [CC0603(1608)]
C186  100nF  [CC0603(1608)]
C187  100nF  [CC0603(1608)]
C188  100nF  [CC0603(1608)]
C189  100nF  [CC0603(1608)]
C190  100nF  [CC0603(1608)]
C191  100nF  [CC0603(1608)]
C192  100nF  [CC0603(1608)]
C193  100nF  [CC0603(1608)]
C194  100nF  [CC0603(1608)]
C195  100nF  [CC0603(1608)]
C196  100nF  [CC0603(1608)]
C197  100nF  [CC0603(1608)]
C198  100nF  [CC0603(1608)]
C199  100nF  [CC0603(1608)]
C200  100nF  [CC0603(1608)]
C201  100nF  [CC0603(1608)]
C202  100nF  [CC0603(1608)]
C203  100nF  [CC0603(1608)]
C204  100nF  [CC0603(1608)]
C205  100nF  [CC0603(1608)]
C206  100nF  [CC0603(1608)]
C207  100nF  [CC0603(1608)]
C208  100nF  [CC0603(1608)]
C209  100nF  [CC0603(1608)]
C210  100nF  [CC0603(1608)]
C211  100nF  [CC0603(1608)]
C212  100nF  [CC0603(1608)]
C213  100nF  [CC0603(1608)]
C214  100nF  [CC0603(1608)]
C215  100nF  [CC0603(1608)]
C216  100nF  [CC0603(1608)]
C217  100nF  [CC0603(1608)]
C218  100nF  [CC0603(1608)]
C219  100nF  [CC0603(1608)]
C220  100nF  [CC0603(1608)]
C221  100nF  [CC0603(1608)]
C222  100nF  [CC0603(1608)]
C223  100nF  [CC0603(1608)]
C224  100nF  [CC0603(1608)]
C225  100nF  [CC0603(1608)]
C226  100nF  [CC0603(1608)]
C227  100nF  [CC0603(1608)]
C228  100nF  [CC0603(1608)]
C229  100nF  [CC0603(1608)]
C230  100nF  [CC0603(1608)]
C231  100nF  [CC0603(1608)]
C232  100nF  [CC0603(1608)]
C233  100nF  [CC0603(1608)]
C234  100nF  [CC0603(1608)]
C235  100nF  [CC0603(1608)]
C236  100nF  [CC0603(1608)]
C237  100nF  [CC0603(1608)]
C238  100nF  [CC0603(1608)]
C239  100nF  [CC0603(1608)]
C240  100nF  [CC0603(1608)]
C241  100nF  [CC0603(1608)]
C242  100nF  [CC0603(1608)]
C243  100nF  [CC0603(1608)]
C244  100nF  [CC0603(1608)]
C245  100nF  [CC0603(1608)]
C246  100nF  [CC0603(1608)]
C247  100nF  [CC0603(1608)]
C248  100nF  [CC0603(1608)]
C249  100nF  [CC0603(1608)]
C250  100nF  [CC0603(1608)]
C251  100nF  [CC0603(1608)]
C252  100nF  [CC0603(1608)]
C253  100nF  [CC0603(1608)]
C254  100nF  [CC0603(1608)]
C255  100nF  [CC0603(1608)]
C256  100nF  [CC0603(1608)]
C257  100nF  [CC0603(1608)]
C258  100nF  [CC0603(1608)]
C259  100nF  [CC0603(1608)]
C260  100nF  [CC0603(1608)]
C261  100nF  [CC0603(1608)]
C262  100nF  [CC0603(1608)]
C263  100nF  [CC0603(1608)]
C264  100nF  [CC0603(1608)]
C265  100nF  [CC0603(1608)]
C266  100nF  [CC0603(1608)]
C267  100nF  [CC0603(1608)]
C268  100nF  [CC0603(1608)]
C269  100nF  [CC0603(1608)]
C270  100nF  [CC0603(1608)]
C271  100nF  [CC0603(1608)]
C272  100nF  [CC0603(1608)]
C273  100nF  [CC0603(1608)]
C274  100nF  [CC0603(1608)]
C275  100nF  [CC0603(1608)]
C276  100nF  [CC0603(1608)]
C277  100nF  [CC0603(1608)]
C278  100nF  [CC0603(1608)]
C279  100nF  [CC0603(1608)]
C280  100nF  [CC0603(1608)]
C281  100nF  [CC0603(1608)]
C282  100nF  [CC0603(1608)]
C283  100nF  [CC0603(1608)]
FB9  600/100M  [FB0603(1608)]
FB10  600/100M  [FB0603(1608)]
FB11  600/100M  [FB0603(1608)]
FB12  600/100M  [FB0603(1608)]
FB13  600/100M  [FB0603(1608)]
FB14  600/100M  [FB0603(1608)]
FB15  600/100M  [FB0603(1608)]
FB16  600/100M  [FB0603(1608)]
M9  Mount Hole  [MHOLE2]
M10  Mount Hole  [MHOLE2]
M11  Mount Hole  [MHOLE2]
M12  Mount Hole  [MHOLE2]
M13  Mount Hole  [MHOLE2]
TP49  TP  [TP_SMD]
TP50  TP  [TP_SMD]
TP51  TP  [TP_SMD]
TP52  TP  [TP_SMD]
TP53  TP  [TP_SMD]
TP54  TP  [TP_SMD]
TP55  TP  [TP_SMD]
TP56  TP  [TP_SMD]
TP57  TP  [TP_SMD]
TP58  TP  [TP_SMD]
TP59  TP  [TP_SMD]
TP60  TP  [TP_SMD]
TP61  TP  [TP_SMD]
TP62  TP  [TP_SMD]
TP63  TP  [TP_SMD]
TP64  TP  [TP_SMD]
TP65  TP  [TP_SMD]
TP66  TP  [TP_SMD]
TP67  TP  [TP_SMD]
TP68  TP  [TP_SMD]
TP69  TP  [TP_SMD]
TP70  TP  [TP_SMD]
TP71  TP  [TP_SMD]
TP72  TP  [TP_SMD]
TP73  TP  [TP_SMD]
TP74  TP  [TP_SMD]
TP75  TP  [TP_SMD]
TP76  TP  [TP_SMD]
TP77  TP  [TP_SMD]
TP78  TP  [TP_SMD]
TP79  TP  [TP_SMD]
TP80  TP  [TP_SMD]
TP81  TP  [TP_SMD]
TP82  TP  [TP_SMD]
TP83  TP  [TP_SMD]
TP84  TP  [TP_SMD]
TP85  TP  [TP_SMD]
TP86  TP  [TP_SMD]
TP87  TP  [TP_SMD]
TP88  TP  [TP_SMD]
U11  BM1380  [QFN56]
U12  BM1380  [QFN56]
U13  BM1380  [QFN56]
U14  BM1380  [QFN56]
U15  BM1380  [QFN56]
U16  BM1380  [QFN56]
U17  BM1380  [QFN56]
U18  BM1380  [QFN56]

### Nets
+3.3V: C164.2 C165.2 C166.2 C167.2 C168.2 C169.2 C170.2 C171.2 C172.2 C173.2 C174.2 C175.2 C228.2 C229.2 C230.2 C231.2 C232.2 C233.2 C234.2 C235.2 C236.2 C237.2 C238.2 C239.2 U11.14(VCC) U11.27(ADDR6) U11.29(VCC) U11.43(VCC) U12.14(VCC) U12.20(ADDR3) U12.27(ADDR6) U12.29(VCC) U12.43(VCC) U13.14(VCC) U13.23(ADDR4) U13.27(ADDR6) U13.29(VCC) U13.43(VCC) U14.14(VCC) U14.20(ADDR3) U14.23(ADDR4) U14.27(ADDR6) U14.29(VCC) U14.43(VCC) U15.14(VCC) U15.24(ADDR5) U15.27(ADDR6) U15.29(VCC) U15.43(VCC) U16.14(VCC) U16.20(ADDR3) U16.24(ADDR5) U16.27(ADDR6) U16.29(VCC) U16.43(VCC) U17.14(VCC) U17.23(ADDR4) U17.24(ADDR5) U17.27(ADDR6) U17.29(VCC) U17.43(VCC) U18.14(VCC) U18.20(ADDR3) U18.23(ADDR4) U18.24(ADDR5) U18.27(ADDR6) U18.29(VCC) U18.43(VCC)
GND: C152.2 C153.2 C154.1 C155.1 C156.2 C157.1 C158.2 C159.1 C160.2 C161.1 C162.2 C163.1 C164.1 C165.1 C166.1 C167.1 C168.1 C169.1 C170.1 C171.1 C172.1 C173.1 C174.1 C175.1 C176.1 C177.1 C178.1 C179.1 C180.1 C181.1 C182.1 C183.1 C184.1 C185.1 C186.1 C187.1 C188.1 C189.1 C190.1 C191.1 C192.1 C193.1 C194.1 C195.1 C196.1 C197.1 C198.1 C199.1 C200.1 C201.1 C202.1 C203.1 C204.1 C205.1 C206.1 C207.1 C208.1 C209.1 C210.1 C211.1 C212.1 C213.1 C214.1 C215.1 C216.1 C217.1 C218.1 C219.1 C220.2 C221.1 C222.2 C223.1 C224.2 C225.1 C226.2 C227.1 C228.1 C229.1 C230.1 C231.1 C232.1 C233.1 C234.1 C235.1 C236.1 C237.1 C238.1 C239.1 C240.1 C241.1 C242.1 C243.1 C244.1 C245.1 C246.1 C247.1 C248.1 C249.1 C250.1 C251.1 C252.1 C253.1 C254.1 C255.1 C256.1 C257.1 C258.1 C259.1 C260.1 C261.1 C262.1 C263.1 C264.1 C265.1 C266.1 C267.1 C268.1 C269.1 C270.1 C271.1 C272.1 C273.1 C274.1 C275.1 C276.1 C277.1 C278.1 C279.1 C280.1 C281.1 C282.1 C283.1 M9.0(PIN) M10.0(PIN) M11.0(PIN) M12.0(PIN) M13.0(PIN) U11.3(GND) U11.8(GND) U11.12(GND) U11.13(VSS) U11.15(ADDR0) U11.16(ADDR1) U11.18(GND) U11.19(ADDR2) U11.20(ADDR3) U11.22(GND) U11.23(ADDR4) U11.24(ADDR5) U11.26(GND) U11.28(ADDR7) U11.30(VSS) U11.31(GND) U11.35(GND) U11.41(GND) U11.42(VSS) U11.45(SMODE) U11.46(GND) U11.50(TEST) U11.52(GND) U11.53(PLL_DVSS) U11.56(PLL_AVSS) U11.57(GND) U12.3(GND) U12.8(GND) U12.12(GND) U12.13(VSS) U12.15(ADDR0) U12.16(ADDR1) U12.18(GND) U12.19(ADDR2) U12.22(GND) U12.23(ADDR4) U12.24(ADDR5) U12.26(GND) U12.28(ADDR7) U12.30(VSS) U12.31(GND) U12.35(GND) U12.41(GND) U12.42(VSS) U12.45(SMODE) U12.46(GND) U12.50(TEST) U12.52(GND) U12.53(PLL_DVSS) U12.56(PLL_AVSS) U12.57(GND) U13.3(GND) U13.8(GND) U13.12(GND) U13.13(VSS) U13.15(ADDR0) U13.16(ADDR1) U13.18(GND) U13.19(ADDR2) U13.20(ADDR3) U13.22(GND) U13.24(ADDR5) U13.26(GND) U13.28(ADDR7) U13.30(VSS) U13.31(GND) U13.35(GND) U13.41(GND) U13.42(VSS) U13.45(SMODE) U13.46(GND) U13.50(TEST) U13.52(GND) U13.53(PLL_DVSS) U13.56(PLL_AVSS) U13.57(GND) U14.3(GND) U14.8(GND) U14.12(GND) U14.13(VSS) U14.15(ADDR0) U14.16(ADDR1) U14.18(GND) U14.19(ADDR2) U14.22(GND) U14.24(ADDR5) U14.26(GND) U14.28(ADDR7) U14.30(VSS) U14.31(GND) U14.35(GND) U14.41(GND) U14.42(VSS) U14.45(SMODE) U14.46(GND) U14.50(TEST) U14.52(GND) U14.53(PLL_DVSS) U14.56(PLL_AVSS) U14.57(GND) U15.3(GND) U15.8(GND) U15.12(GND) U15.13(VSS) U15.15(ADDR0) U15.16(ADDR1) U15.18(GND) U15.19(ADDR2) U15.20(ADDR3) U15.22(GND) U15.23(ADDR4) U15.26(GND) U15.28(ADDR7) U15.30(VSS) U15.31(GND) U15.35(GND) U15.41(GND) U15.42(VSS) U15.45(SMODE) U15.46(GND) U15.50(TEST) U15.52(GND) U15.53(PLL_DVSS) U15.56(PLL_AVSS) U15.57(GND) U16.3(GND) U16.8(GND) U16.12(GND) U16.13(VSS) U16.15(ADDR0) U16.16(ADDR1) U16.18(GND) U16.19(ADDR2) U16.22(GND) U16.23(ADDR4) U16.26(GND) U16.28(ADDR7) U16.30(VSS) U16.31(GND) U16.35(GND) U16.41(GND) U16.42(VSS) U16.45(SMODE) U16.46(GND) U16.50(TEST) U16.52(GND) U16.53(PLL_DVSS) U16.56(PLL_AVSS) U16.57(GND) U17.3(GND) U17.8(GND) U17.12(GND) U17.13(VSS) U17.15(ADDR0) U17.16(ADDR1) U17.18(GND) U17.19(ADDR2) U17.20(ADDR3) U17.22(GND) U17.26(GND) U17.28(ADDR7) U17.30(VSS) U17.31(GND) U17.35(GND) U17.41(GND) U17.42(VSS) U17.45(SMODE) U17.46(GND) U17.50(TEST) U17.52(GND) U17.53(PLL_DVSS) U17.56(PLL_AVSS) U17.57(GND) U18.3(GND) U18.8(GND) U18.12(GND) U18.13(VSS) U18.15(ADDR0) U18.16(ADDR1) U18.18(GND) U18.19(ADDR2) U18.22(GND) U18.26(GND) U18.28(ADDR7) U18.30(VSS) U18.31(GND) U18.35(GND) U18.41(GND) U18.42(VSS) U18.45(SMODE) U18.46(GND) U18.50(TEST) U18.52(GND) U18.53(PLL_DVSS) U18.56(PLL_AVSS) U18.57(GND)
VDD2: C152.1 C153.1 C154.2 C155.2 C176.2 C177.2 C178.2 C179.2 C180.2 C181.2 C182.2 C183.2 C184.2 C185.2 C186.2 C187.2 C188.2 C189.2 C190.2 C191.2 C192.2 C193.2 C194.2 C195.2 C196.2 C197.2 C198.2 C199.2 C200.2 C201.2 C202.2 C203.2 C204.2 C205.2 C206.2 C207.2 C208.2 C209.2 C210.2 C211.2 C212.2 C213.2 C214.2 C215.2 C216.2 C217.2 C218.2 C219.2 C240.2 C241.2 C242.2 C243.2 C244.2 C245.2 C246.2 C247.2 C248.2 C249.2 C250.2 C251.2 C252.2 C253.2 C254.2 C255.2 C256.2 C257.2 C258.2 C259.2 C260.2 C261.2 C262.2 C263.2 C264.2 C265.2 C266.2 C267.2 C268.2 C269.2 C270.2 C271.2 C272.2 C273.2 C274.2 C275.2 C276.2 C277.2 C278.2 C279.2 C280.2 C281.2 C282.2 C283.2 U11.4(VDD) U11.7(VDD) U11.11(VDD) U11.17(VDD) U11.21(VDD) U11.25(VDD) U11.32(VDD) U11.36(VDD) U11.40(VDD) U11.47(VDD) U11.51(VDD) U12.4(VDD) U12.7(VDD) U12.11(VDD) U12.17(VDD) U12.21(VDD) U12.25(VDD) U12.32(VDD) U12.36(VDD) U12.40(VDD) U12.47(VDD) U12.51(VDD) U13.4(VDD) U13.7(VDD) U13.11(VDD) U13.17(VDD) U13.21(VDD) U13.25(VDD) U13.32(VDD) U13.36(VDD) U13.40(VDD) U13.47(VDD) U13.51(VDD) U14.4(VDD) U14.7(VDD) U14.11(VDD) U14.17(VDD) U14.21(VDD) U14.25(VDD) U14.32(VDD) U14.36(VDD) U14.40(VDD) U14.47(VDD) U14.51(VDD) U15.4(VDD) U15.7(VDD) U15.11(VDD) U15.17(VDD) U15.21(VDD) U15.25(VDD) U15.32(VDD) U15.36(VDD) U15.40(VDD) U15.47(VDD) U15.51(VDD) U16.4(VDD) U16.7(VDD) U16.11(VDD) U16.17(VDD) U16.21(VDD) U16.25(VDD) U16.32(VDD) U16.36(VDD) U16.40(VDD) U16.47(VDD) U16.51(VDD) U17.4(VDD) U17.7(VDD) U17.11(VDD) U17.17(VDD) U17.21(VDD) U17.25(VDD) U17.32(VDD) U17.36(VDD) U17.40(VDD) U17.47(VDD) U17.51(VDD) U18.4(VDD) U18.7(VDD) U18.11(VDD) U18.17(VDD) U18.21(VDD) U18.25(VDD) U18.32(VDD) U18.36(VDD) U18.40(VDD) U18.47(VDD) U18.51(VDD)
VPLL2: C156.1 C158.1 C160.1 C162.1 C220.1 C222.1 C224.1 C226.1 FB9.2 FB10.2 FB11.2 FB12.2 FB13.2 FB14.2 FB15.2 FB16.2 U11.54(PLL_DVDD) U12.54(PLL_DVDD) U13.54(PLL_DVDD) U14.54(PLL_DVDD) U15.54(PLL_DVDD) U16.54(PLL_DVDD) U17.54(PLL_DVDD) U18.54(PLL_DVDD)
BO8: U11.9(BI)
BO9: TP49.1 U11.34(BO) U12.9(BI)
BO10: TP50.1 U12.34(BO) U13.9(BI)
BO11: TP51.1 U13.34(BO) U14.9(BI)
BO12: TP52.1 U14.34(BO) U15.9(BI)
BO13: TP70.1 U15.34(BO) U16.9(BI)
BO14: TP71.1 U16.34(BO) U17.9(BI)
BO15: TP72.1 U17.34(BO) U18.9(BI)
BO16: TP69.1 U18.34(BO)
CLK8: U11.1(XIN)
CLK9: TP62.1 U11.39(CLKOUT) U12.1(XIN)
CLK10: TP64.1 U12.39(CLKOUT) U13.1(XIN)
CLK11: TP66.1 U13.39(CLKOUT) U14.1(XIN)
CLK12: TP68.1 U14.39(CLKOUT) U15.1(XIN)
CLK13: TP84.1 U15.39(CLKOUT) U16.1(XIN)
CLK14: TP86.1 U16.39(CLKOUT) U17.1(XIN)
CLK15: TP88.1 U17.39(CLKOUT) U18.1(XIN)
CLK16: TP82.1 U18.39(CLKOUT)
CO8: U11.5(CI)
CO9: TP53.1 U11.38(CO) U12.5(CI)
CO10: TP55.1 U12.38(CO) U13.5(CI)
CO11: TP57.1 U13.38(CO) U14.5(CI)
CO12: TP59.1 U14.38(CO) U15.5(CI)
CO13: TP75.1 U15.38(CO) U16.5(CI)
CO14: TP77.1 U16.38(CO) U17.5(CI)
CO15: TP79.1 U17.38(CO) U18.5(CI)
CO16: TP73.1 U18.38(CO)
RI8: U11.6(RO)
RI9: TP54.1 U11.37(RI) U12.6(RO)
RI10: TP56.1 U12.37(RI) U13.6(RO)
RI11: TP58.1 U13.37(RI) U14.6(RO)
RI12: TP60.1 U14.37(RI) U15.6(RO)
RI13: TP76.1 U15.37(RI) U16.6(RO)
RI14: TP78.1 U16.37(RI) U17.6(RO)
RI15: TP80.1 U17.37(RI) U18.6(RO)
RI16: TP74.1 U18.37(RI)
RST8: U11.10(RST_N)
RST9: TP61.1 U11.33(NRSTO) U12.10(RST_N)
RST10: TP63.1 U12.33(NRSTO) U13.10(RST_N)
RST11: TP65.1 U13.33(NRSTO) U14.10(RST_N)
RST12: TP67.1 U14.33(NRSTO) U15.10(RST_N)
RST13: TP83.1 U15.33(NRSTO) U16.10(RST_N)
RST14: TP85.1 U16.33(NRSTO) U17.10(RST_N)
RST15: TP87.1 U17.33(NRSTO) U18.10(RST_N)
RST16: TP81.1 U18.33(NRSTO)
NetC157_2: C157.2 FB9.1 U11.55(PLL_AVDD)
NetC159_2: C159.2 FB10.1 U12.55(PLL_AVDD)
NetC161_2: C161.2 FB11.1 U13.55(PLL_AVDD)
NetC163_2: C163.2 FB12.1 U14.55(PLL_AVDD)
NetC221_2: C221.2 FB13.1 U15.55(PLL_AVDD)
NetC223_2: C223.2 FB14.1 U16.55(PLL_AVDD)
NetC225_2: C225.2 FB15.1 U17.55(PLL_AVDD)
NetC227_2: C227.2 FB16.1 U18.55(PLL_AVDD)

Not connected (* = marked no-connect by the designer): U11 2(XOUT)* 44(CMODE)* 48(TF)* 49(RF)*; U12 2(XOUT)* 44(CMODE)* 48(TF)* 49(RF)*; U13 2(XOUT)* 44(CMODE)* 48(TF)* 49(RF)*; U14 2(XOUT)* 44(CMODE)* 48(TF)* 49(RF)*; U15 2(XOUT)* 44(CMODE)* 48(TF)* 49(RF)*; U16 2(XOUT)* 44(CMODE)* 48(TF)* 49(RF)*; U17 2(XOUT)* 44(CMODE)* 48(TF)* 49(RF)*; U18 2(XOUT)* 44(CMODE)* 48(TF)* 49(RF)*

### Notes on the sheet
- ADDR:0x40
- ADDR:0x48
- ADDR:0x50
- ADDR:0x58
- ADDR:0x60
- ADDR:0x68
- ADDR:0x70
- ADDR:0x78

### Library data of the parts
C152 C153 = T492C: as C17 on sheet HashUnit1
C154 C155 = Cap Semi: Capacitor (Semiconductor SIM Model)
C156-C283 = Cap: Capacitor
FB9-FB16 = FB: Inductor; Code_IEC: 1005
M9-M13 = M_Hole
TP49-TP88 = TP: Test Point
